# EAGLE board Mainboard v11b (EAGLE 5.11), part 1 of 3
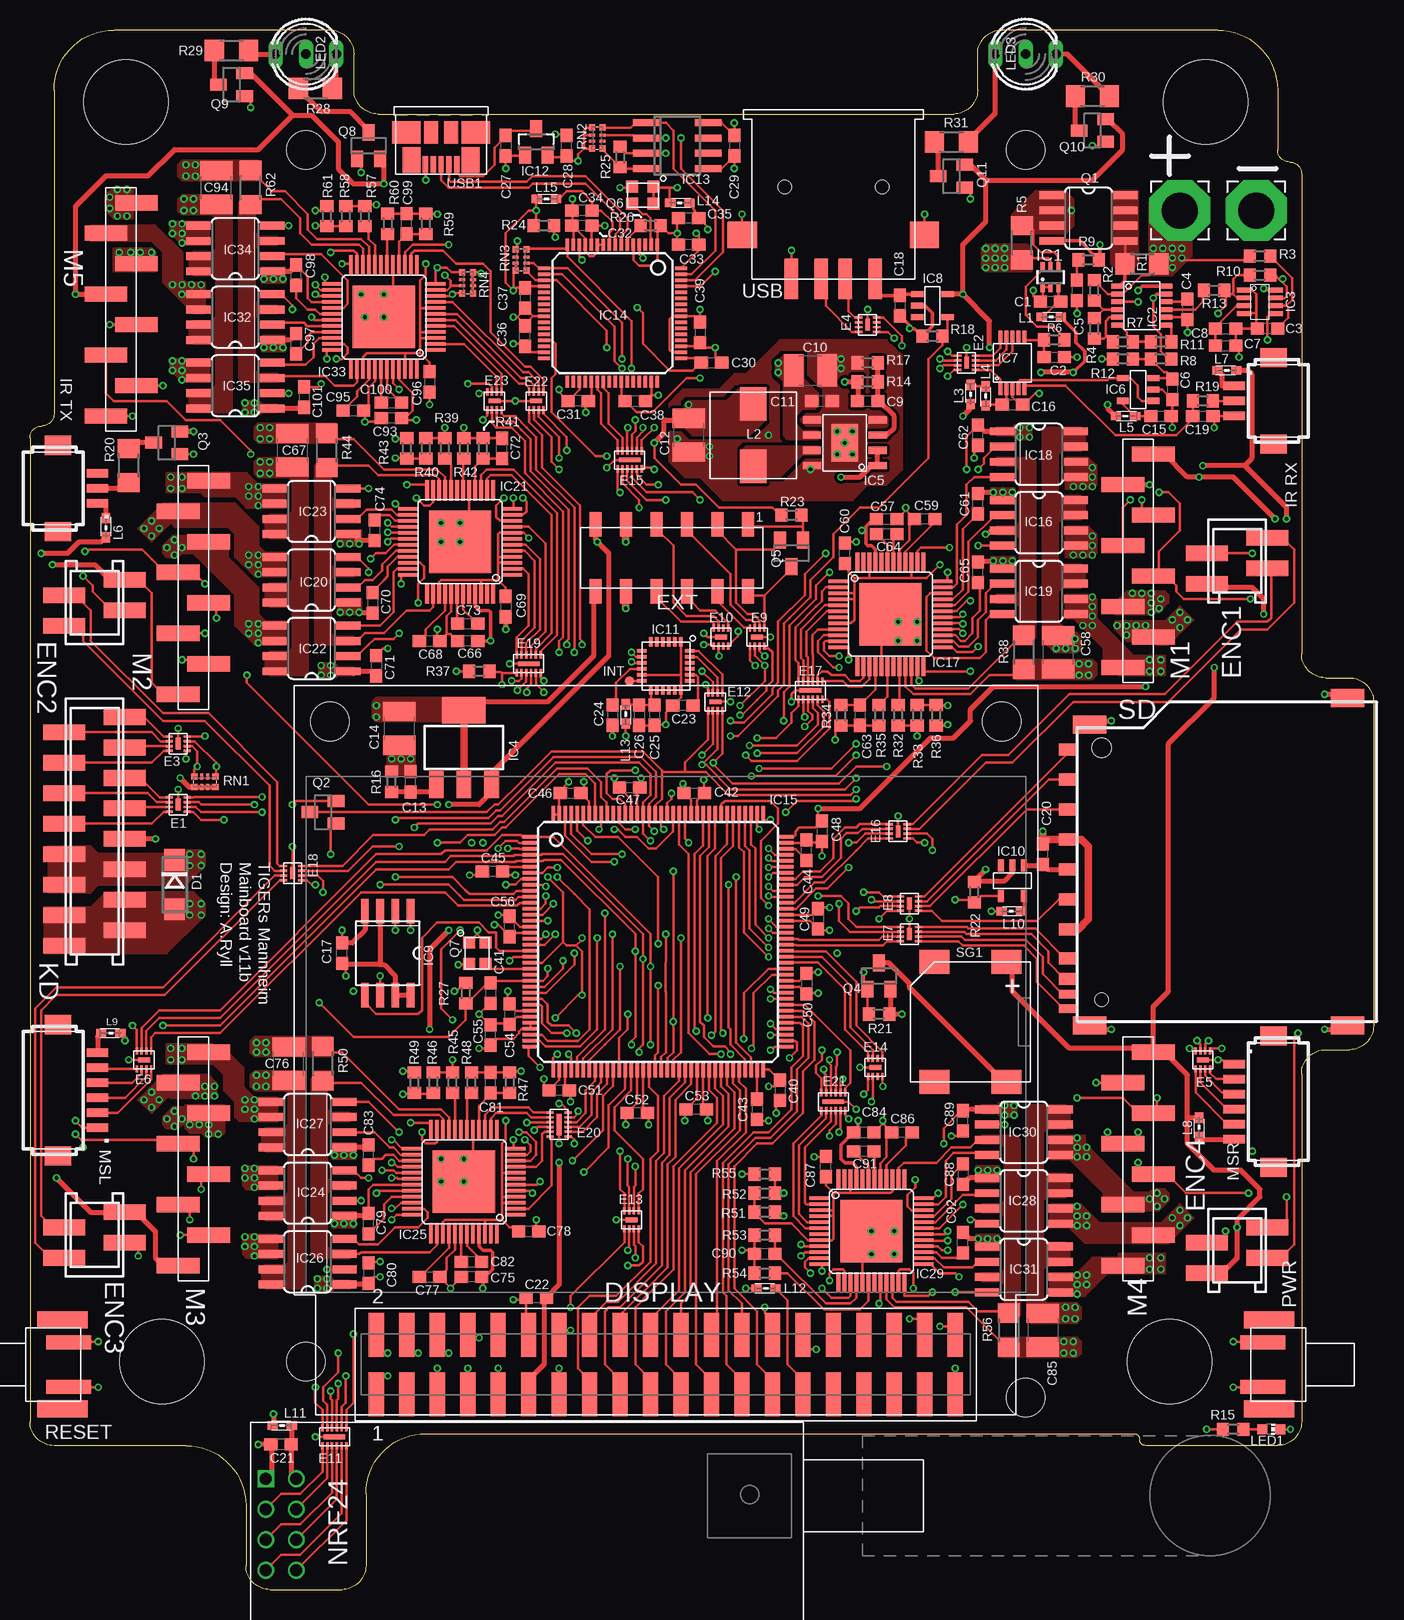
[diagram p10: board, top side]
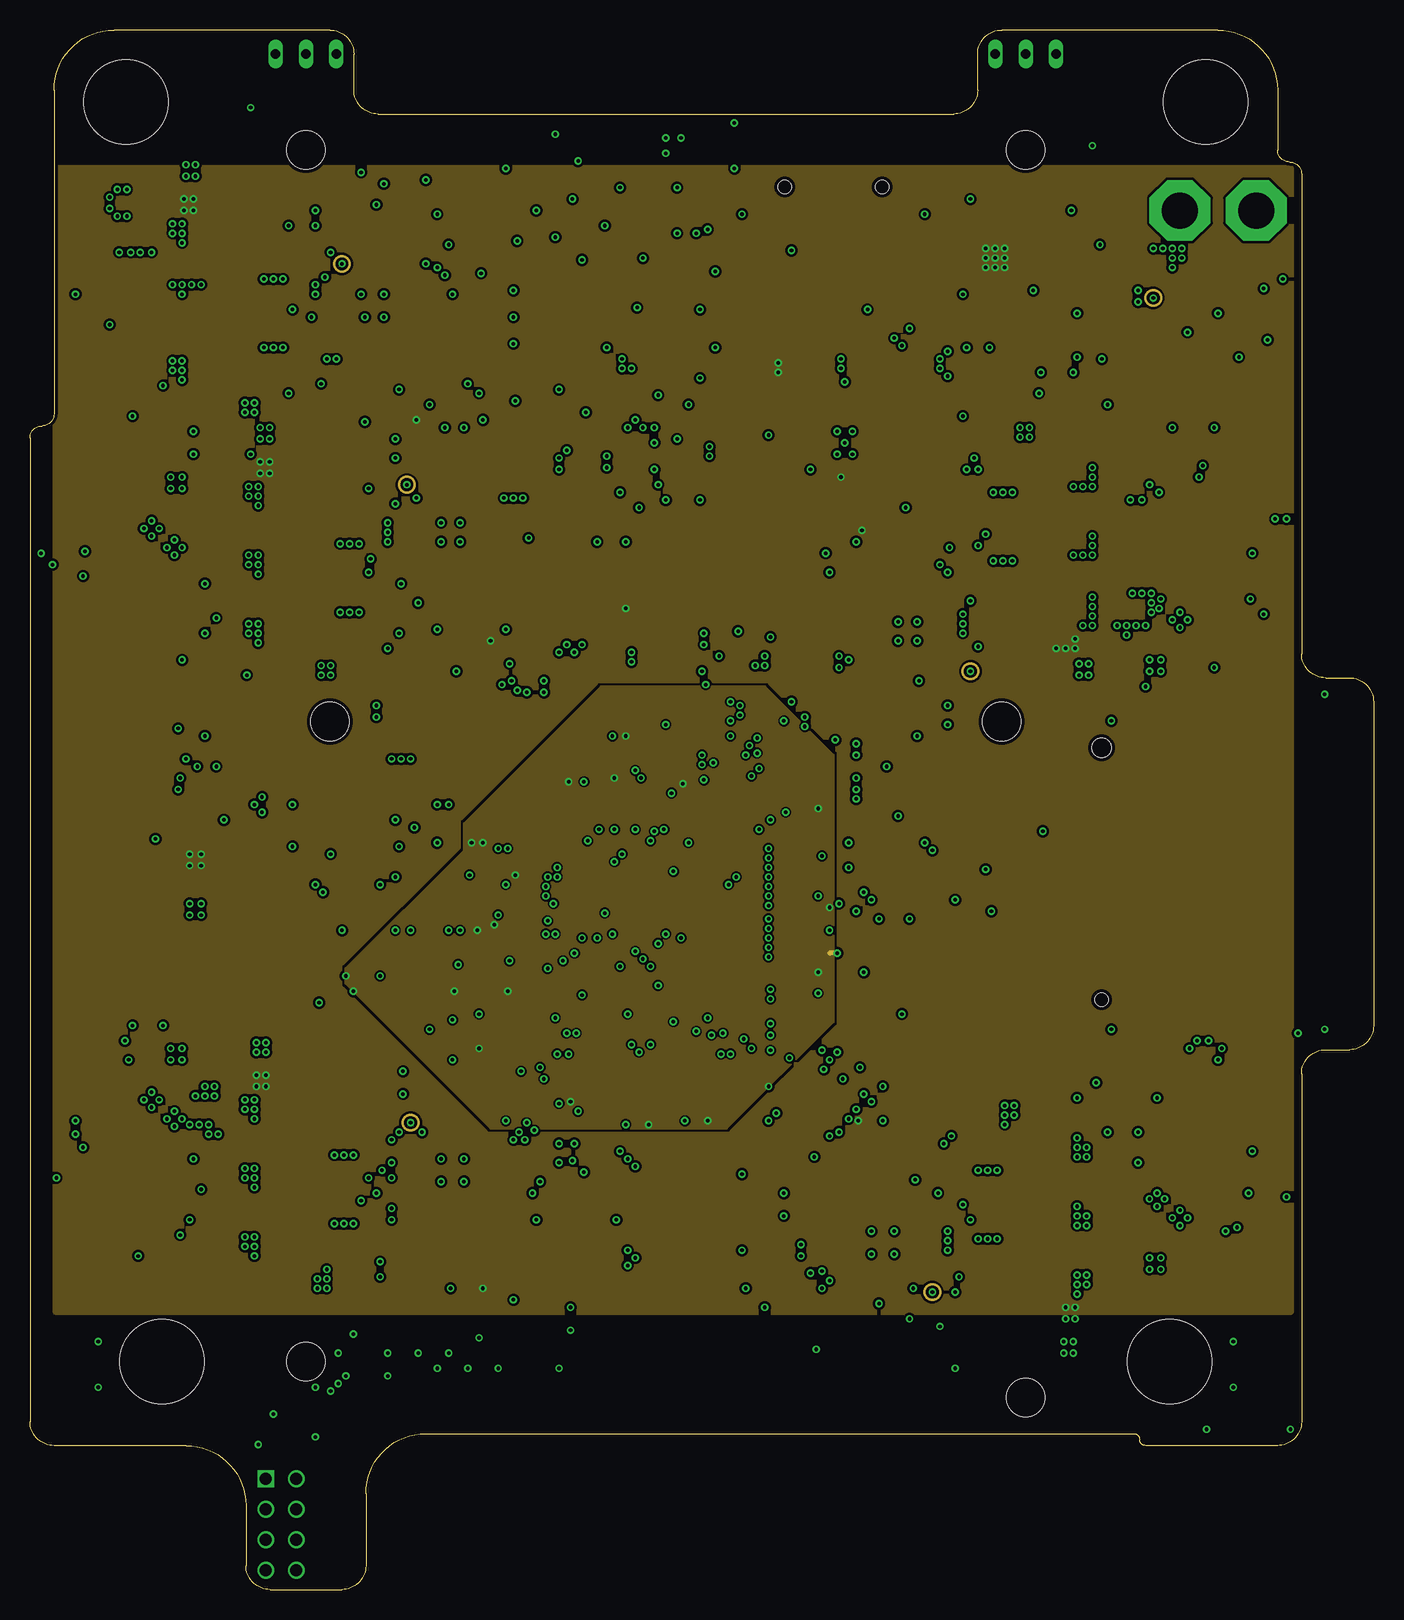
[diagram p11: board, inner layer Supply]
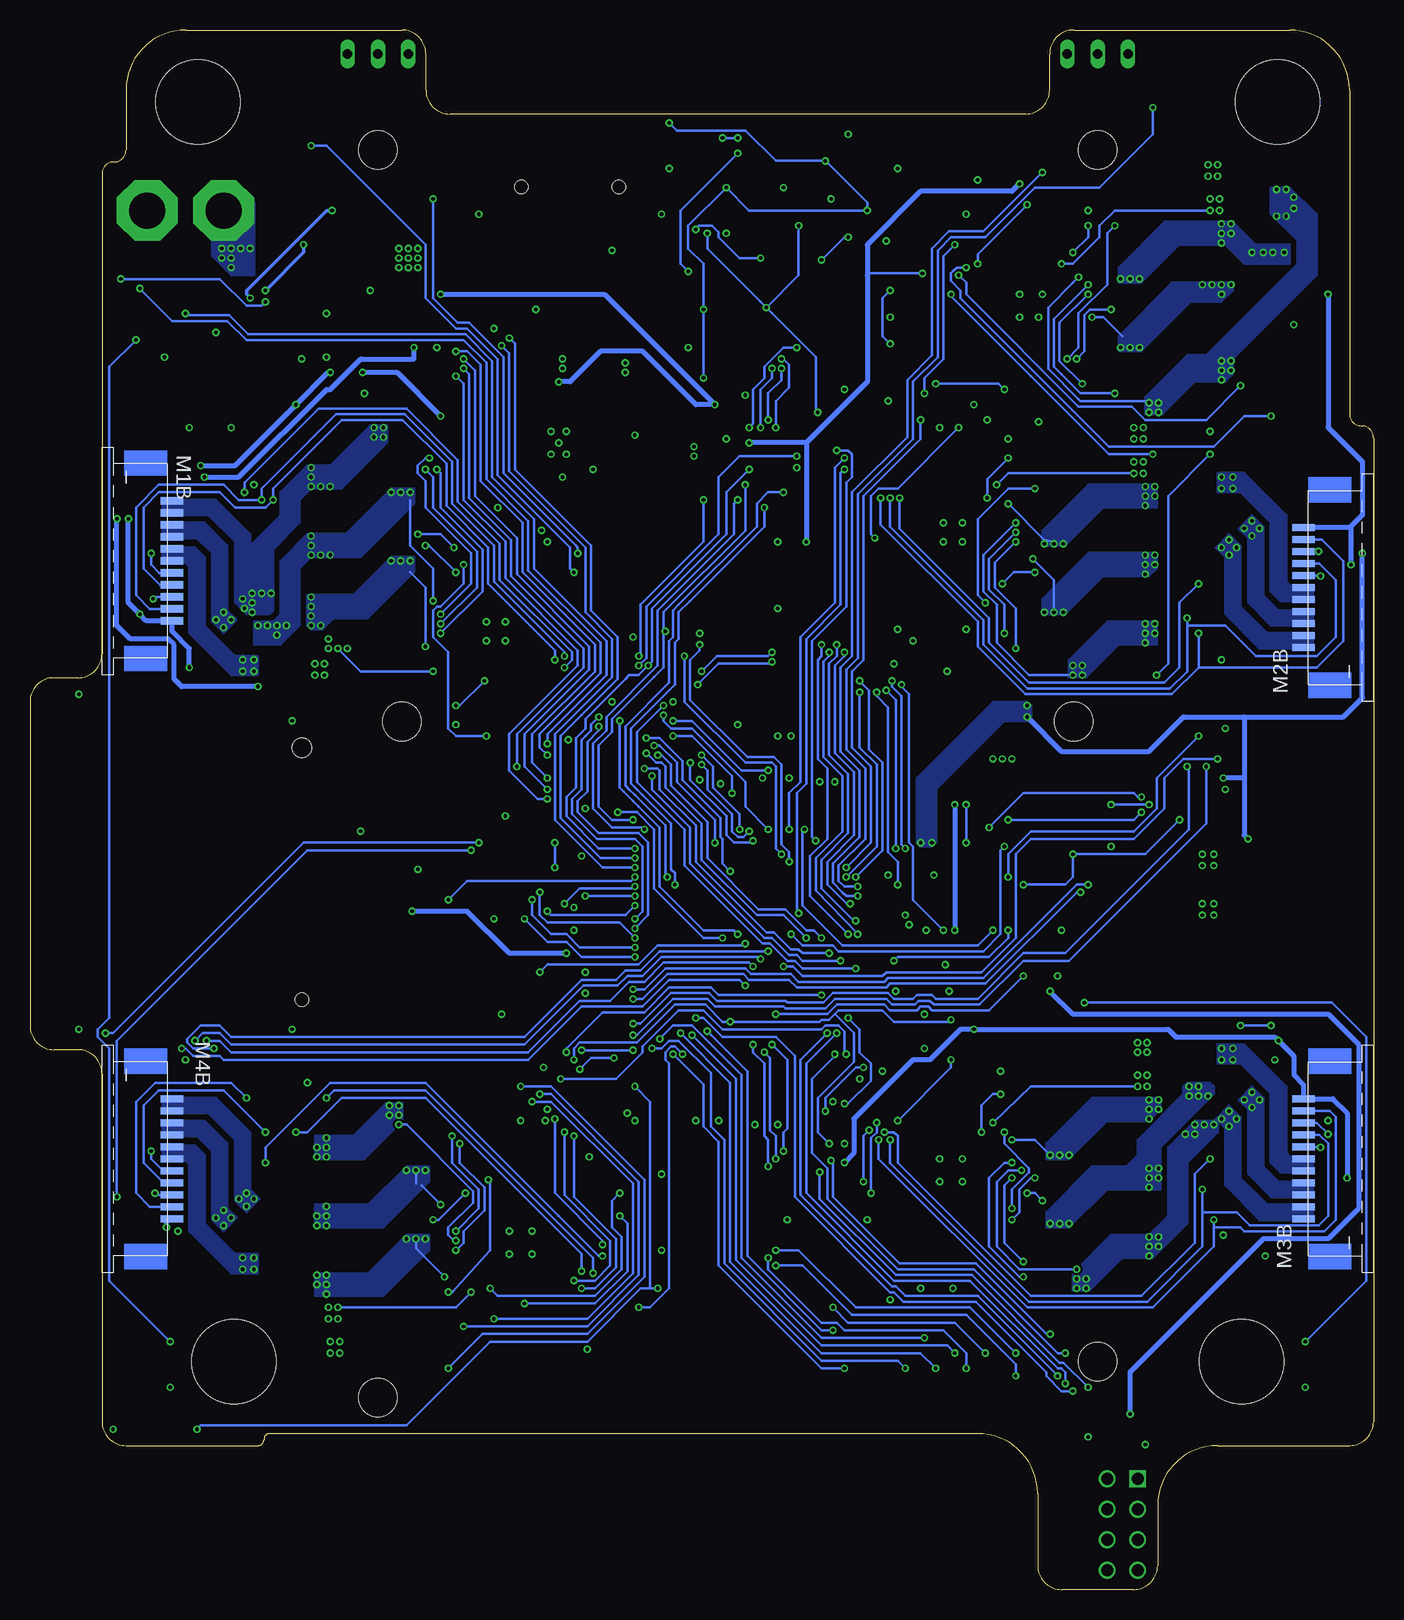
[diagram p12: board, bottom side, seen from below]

Size 112 x 130 mm. Coordinates in mm from the lower left corner, seen from the top.
Outline: 0,96 0,14 arc90 2,12 13,12 arc-90 18,7 18,2 arc90 20,0 26,0 arc90 28,2 28,8 arc-90 33,13 92,13 arc-90 92.5,12.5 arc90 93,12 104,12 arc90 106,14 106,43 arc-90 108,45 110,45 arc90 112,47 112,74 arc90 110,76 108,76 arc-90 106,78 106,118 arc90 105,119 arc-90 104,120 104,125 arc90 99,130 81,130 arc90 79,128 79,125 arc-90 77,123 29,123 arc-90 27,125 27,128 arc90 25,130 7,130 arc90 2,125 2,98 arc-90 1,97 arc90 0,96
Copper layers (1+2*15+16): Top 0.035mm / dielectric 0.38mm / $GND 0.035mm / dielectric 0.71mm / Supply 0.035mm / dielectric 0.38mm / Bottom 0.035mm
Design rules "PCB-POOL Standard_ML4 *": minimum track width 0.15mm, minimum drill 0.3mm, track to track 0.15mm, track to pad 0.15mm, pad to pad 0.15mm, via to via 0.15mm, smd to smd 0.15mm, copper to edge 0.3mm, drill to drill 0.2mm, minimum pad ring 0.2mm, minimum via ring 0.15mm, stop-mask expansion 0.075mm, vias tented up to drill 0mil, thermal gap 0.2mm
Net classes: 0 default: width 0.152 mm, clearance 0.152 mm
Holes 7 mm at 8,124 98,124 95,19 11,19
Holes 3.2 mm at 23,120 83,120 23,19 83,16
tKeepout: area 1.5,117.5 to 14.5,130.5; area 91.5,117.5 to 104.5,130.5; area 4.5,12.5 to 17.5,25.5; area 88.5,12.5 to 101.5,25.5; area 79.6,116.6 to 86.4,123.4; area 19.6,116.6 to 26.4,123.4; area 19.6,15.6 to 26.4,22.4; area 79.6,12.6 to 86.4,19.4

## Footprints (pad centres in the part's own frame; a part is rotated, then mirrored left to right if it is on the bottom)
5,08/3 = drill 3 pad 5.08 octagon: P$1 0,0
C0603 = smd 1.1 x 1: 1 -0.85,0; 2 0.85,0
C1210 = smd 1.6 x 2.7: 1 -1.4,0; 2 1.4,0
DO214AC = smd 1.8 x 1.7: A 2.05,0; C -2.05,0
LT24 = smd 1.27 x 3.683: 1 24.13,2.477; 2 24.13,-2.477; 3 21.59,2.477; 4 21.59,-2.477; 5 19.05,2.477; 6 19.05,-2.477; 7 16.51,2.477; 8 16.51,-2.477; 9 13.97,2.477; 10 13.97,-2.477; 11 11.43,2.477; 12 11.43,-2.477; 13 8.89,2.477; 14 8.89,-2.477; 15 6.35,2.477; 16 6.35,-2.477; 17 3.81,2.477; 18 3.81,-2.477; 19 1.27,2.477; 20 1.27,-2.477; 21 -1.27,2.477; 22 -1.27,-2.477; 23 -3.81,2.477; 24 -3.81,-2.477; 25 -6.35,2.477; 26 -6.35,-2.477; 27 -8.89,2.477; 28 -8.89,-2.477; 29 -11.43,2.477; 30 -11.43,-2.477; 31 -13.97,2.477; 32 -13.97,-2.477; 33 -16.51,2.477; 34 -16.51,-2.477; 35 -19.05,2.477; 36 -19.05,-2.477; 37 -21.59,2.477; 38 -21.59,-2.477; 39 -24.13,2.477; 40 -24.13,-2.477 | hole 3.2: -28,-53.6; 28,-53.6
QFN17X15 = smd 0.2 x 0.6: 1 -0.6,-0.75; 2 -0.6,0.75; 3 -0.2,-0.75; 4 -0.2,0.75; 5 0.2,-0.75; 6 0.2,0.75; 7 0.6,-0.75; 8 0.6,0.75 | smd 1 x 0.4: GND 0,0
QFN25X15 = smd 0.2 x 0.6: 1 -1,-0.75; 2 -1,0.75; 3 -0.6,-0.75; 4 -0.6,0.75; 5 -0.2,-0.75; 6 -0.2,0.75; 7 0.2,-0.75; 8 0.2,0.75; 9 0.6,-0.75; 10 0.6,0.75; 11 1,-0.75; 12 1,0.75 | smd 1.8 x 0.4: GND 0,0
MMT-F-SMD-4 = smd 1.3 x 3.5: 1 1.905,-2.54; 2 0.635,2.54; 3 -0.635,-2.54; 4 -1.905,2.54
XSM-106-DV = smd 1.016 x 2.032: 1 -6.35,-2.794; 2 -6.35,2.794; 3 -3.81,-2.794; 4 -3.81,2.794; 5 -1.27,-2.794; 6 -1.27,2.794; 7 1.27,-2.794; 8 1.27,2.794; 9 3.81,-2.794; 10 3.81,2.794; 11 6.35,-2.794; 12 6.35,2.794
SC70-6L = smd 0.35 x 0.8: 1 -0.65,-0.85; 2 0,-0.85; 3 0.65,-0.85; 4 0.65,0.85; 5 0,0.85; 6 -0.65,0.85
MSOP-12 = smd 0.42 x 0.95: 1 -1.625,-2.075; 2 -0.975,-2.075; 3 -0.325,-2.075; 4 0.325,-2.075; 5 0.975,-2.075; 6 1.625,-2.075; 7 1.625,2.075; 8 0.975,2.075; 9 0.325,2.075; 10 -0.325,2.075; 11 -0.975,2.075; 12 -1.625,2.075
SOT23-8 = smd 1.22 x 0.4: 1 -1.31,0.975; 2 -1.31,0.325; 3 -1.31,-0.325; 4 -1.31,-0.975; 5 1.31,-0.975; 6 1.31,-0.325; 7 1.31,0.325; 8 1.31,0.975
SOT223 = smd 1.219 x 2.235: 1 -2.311,-3.099; 2 0,-3.099; 3 2.311,-3.099 | smd 3.6 x 2.2: 4 0,3.099
HSOP8 = smd 1.524 x 0.61: 1 -2.743,1.905; 2 -2.743,0.635; 3 -2.743,-0.635; 4 -2.743,-1.905; 5 2.743,-1.905; 6 2.743,-0.635; 7 2.743,0.635; 8 2.743,1.905 | smd 2.2 x 3.1: PAD 0,0
SOT23-5 = smd 1.016 x 0.508: 1 -1.27,0.953; 2 -1.27,0; 3 -1.27,-0.953; 4 1.27,-0.953; 5 1.27,0.953
MSOP10-2 = smd 0.3 x 1: 1 -1,-2.2; 2 -0.5,-2.2; 3 0,-2.2; 4 0.5,-2.2; 5 1,-2.2; 6 1,2.2; 7 0.5,2.2; 8 0,2.2; 9 -0.5,2.2; 10 -1,2.2
SO08-208 = smd 0.66 x 2.032: 1 -1.905,-3.498; 2 -0.635,-3.498; 3 0.635,-3.498; 4 1.905,-3.498; 5 1.905,3.498; 6 0.635,3.498; 7 -0.635,3.498; 8 -1.905,3.498
QFN4X4-24 = smd 0.8 x 0.3: 1 -2,1.25; 2 -2,0.75; 3 -2,0.25; 4 -2,-0.25; 5 -2,-0.75; 6 -2,-1.25; 13 2,-1.25; 14 2,-0.75; 15 2,-0.25; 16 2,0.25; 17 2,0.75; 18 2,1.25 | smd 0.3 x 0.8: 7 -1.25,-2; 8 -0.75,-2; 9 -0.25,-2; 10 0.25,-2; 11 0.75,-2; 12 1.25,-2; 19 1.25,2; 20 0.75,2; 21 0.25,2; 22 -0.25,2; 23 -0.75,2; 24 -1.25,2
SOT23 = smd 1 x 1.4: 1 -0.95,-1.1; 2 0.95,-1.1; 3 0,1.1
SO-08 = smd 0.6 x 2.2: 1 -1.905,-2.6; 2 -0.635,-2.6; 3 0.635,-2.6; 4 1.905,-2.6; 5 1.905,2.6; 6 0.635,2.6; 7 -0.635,2.6; 8 -1.905,2.6
LQFP64-ST = smd 1 x 0.3: 1 -5.7,3.75; 2 -5.7,3.25; 3 -5.7,2.75; 4 -5.7,2.25; 5 -5.7,1.75; 6 -5.7,1.25; 7 -5.7,0.75; 8 -5.7,0.25; 9 -5.7,-0.25; 10 -5.7,-0.75; 11 -5.7,-1.25; 12 -5.7,-1.75; 13 -5.7,-2.25; 14 -5.7,-2.75; 15 -5.7,-3.25; 16 -5.7,-3.75; 33 5.7,-3.75; 34 5.7,-3.25; 35 5.7,-2.75; 36 5.7,-2.25; 37 5.7,-1.75; 38 5.7,-1.25; 39 5.7,-0.75; 40 5.7,-0.25; 41 5.7,0.25; 42 5.7,0.75; 43 5.7,1.25; 44 5.7,1.75; 45 5.7,2.25; 46 5.7,2.75; 47 5.7,3.25; 48 5.7,3.75 | smd 0.3 x 1: 17 -3.75,-5.7; 18 -3.25,-5.7; 19 -2.75,-5.7; 20 -2.25,-5.7; 21 -1.75,-5.7; 22 -1.25,-5.7; 23 -0.75,-5.7; 24 -0.25,-5.7; 25 0.25,-5.7; 26 0.75,-5.7; 27 1.25,-5.7; 28 1.75,-5.7; 29 2.25,-5.7; 30 2.75,-5.7; 31 3.25,-5.7; 32 3.75,-5.7; 49 3.75,5.7; 50 3.25,5.7; 51 2.75,5.7; 52 2.25,5.7; 53 1.75,5.7; 54 1.25,5.7; 55 0.75,5.7; 56 0.25,5.7; 57 -0.25,5.7; 58 -0.75,5.7; 59 -1.25,5.7; 60 -1.75,5.7; 61 -2.25,5.7; 62 -2.75,5.7; 63 -3.25,5.7; 64 -3.75,5.7
LQFP144-ST = smd 0.3 x 1.35: 1 -8.75,-10.625; 2 -8.25,-10.625; 3 -7.75,-10.625; 4 -7.25,-10.625; 5 -6.75,-10.625; 6 -6.25,-10.625; 7 -5.75,-10.625; 8 -5.25,-10.625; 9 -4.75,-10.625; 10 -4.25,-10.625; 11 -3.75,-10.625; 12 -3.25,-10.625; 13 -2.75,-10.625; 14 -2.25,-10.625; 15 -1.75,-10.625; 16 -1.25,-10.625; 17 -0.75,-10.625; 18 -0.25,-10.625; 19 0.25,-10.625; 20 0.75,-10.625; 21 1.25,-10.625; 22 1.75,-10.625; 23 2.25,-10.625; 24 2.75,-10.625; 25 3.25,-10.625; 26 3.75,-10.625; 27 4.25,-10.625; 28 4.75,-10.625; 29 5.25,-10.625; 30 5.75,-10.625; 31 6.25,-10.625; 32 6.75,-10.625; 33 7.25,-10.625; 34 7.75,-10.625; 35 8.25,-10.625; 36 8.75,-10.625; 73 8.75,10.625; 74 8.25,10.625; 75 7.75,10.625; 76 7.25,10.625; 77 6.75,10.625; 78 6.25,10.625; 79 5.75,10.625; 80 5.25,10.625; 81 4.75,10.625; 82 4.25,10.625; 83 3.75,10.625; 84 3.25,10.625; 85 2.75,10.625; 86 2.25,10.625; 87 1.75,10.625; 88 1.25,10.625; 89 0.75,10.625; 90 0.25,10.625; 91 -0.25,10.625; 92 -0.75,10.625; 93 -1.25,10.625; 94 -1.75,10.625; 95 -2.25,10.625; 96 -2.75,10.625; 97 -3.25,10.625; 98 -3.75,10.625; 99 -4.25,10.625; 100 -4.75,10.625; 101 -5.25,10.625; 102 -5.75,10.625; 103 -6.25,10.625; 104 -6.75,10.625; 105 -7.25,10.625; 106 -7.75,10.625; 107 -8.25,10.625; 108 -8.75,10.625 | smd 1.35 x 0.3: 37 10.625,-8.75; 38 10.625,-8.25; 39 10.625,-7.75; 40 10.625,-7.25; 41 10.625,-6.75; 42 10.625,-6.25; 43 10.625,-5.75; 44 10.625,-5.25; 45 10.625,-4.75; 46 10.625,-4.25; 47 10.625,-3.75; 48 10.625,-3.25; 49 10.625,-2.75; 50 10.625,-2.25; 51 10.625,-1.75; 52 10.625,-1.25; 53 10.625,-0.75; 54 10.625,-0.25; 55 10.625,0.25; 56 10.625,0.75; 57 10.625,1.25; 58 10.625,1.75; 59 10.625,2.25; 60 10.625,2.75; 61 10.625,3.25; 62 10.625,3.75; 63 10.625,4.25; 64 10.625,4.75; 65 10.625,5.25; 66 10.625,5.75; 67 10.625,6.25; 68 10.625,6.75; 69 10.625,7.25; 70 10.625,7.75; 71 10.625,8.25; 72 10.625,8.75; 109 -10.625,8.75; 110 -10.625,8.25; 111 -10.625,7.75; 112 -10.625,7.25; 113 -10.625,6.75; 114 -10.625,6.25; 115 -10.625,5.75; 116 -10.625,5.25; 117 -10.625,4.75; 118 -10.625,4.25; 119 -10.625,3.75; 120 -10.625,3.25; 121 -10.625,2.75; 122 -10.625,2.25; 123 -10.625,1.75; 124 -10.625,1.25; 125 -10.625,0.75; 126 -10.625,0.25; 127 -10.625,-0.25; 128 -10.625,-0.75; 129 -10.625,-1.25; 130 -10.625,-1.75; 131 -10.625,-2.25; 132 -10.625,-2.75; 133 -10.625,-3.25; 134 -10.625,-3.75; 135 -10.625,-4.25; 136 -10.625,-4.75; 137 -10.625,-5.25; 138 -10.625,-5.75; 139 -10.625,-6.25; 140 -10.625,-6.75; 141 -10.625,-7.25; 142 -10.625,-7.75; 143 -10.625,-8.25; 144 -10.625,-8.75
SOIC8 = smd 0.66 x 2.032: 1 -1.905,-3.073; 2 -0.635,-3.073; 3 0.635,-3.073; 4 1.905,-3.073; 5 1.905,3.073; 6 0.635,3.073; 7 -0.635,3.073; 8 -1.905,3.073
LQFP48-AL = smd 0.3 x 1.7: 1 -2.75,-4.3; 2 -2.25,-4.3; 3 -1.75,-4.3; 4 -1.25,-4.3; 5 -0.75,-4.3; 6 -0.25,-4.3; 7 0.25,-4.3; 8 0.75,-4.3; 9 1.25,-4.3; 10 1.75,-4.3; 11 2.25,-4.3; 12 2.75,-4.3; 25 2.75,4.3; 26 2.25,4.3; 27 1.75,4.3; 28 1.25,4.3; 29 0.75,4.3; 30 0.25,4.3; 31 -0.25,4.3; 32 -0.75,4.3; 33 -1.25,4.3; 34 -1.75,4.3; 35 -2.25,4.3; 36 -2.75,4.3 | smd 1.7 x 0.3: 13 4.3,-2.75; 14 4.3,-2.25; 15 4.3,-1.75; 16 4.3,-1.25; 17 4.3,-0.75; 18 4.3,-0.25; 19 4.3,0.25; 20 4.3,0.75; 21 4.3,1.25; 22 4.3,1.75; 23 4.3,2.25; 24 4.3,2.75; 37 -4.3,2.75; 38 -4.3,2.25; 39 -4.3,1.75; 40 -4.3,1.25; 41 -4.3,0.75; 42 -4.3,0.25; 43 -4.3,-0.25; 44 -4.3,-0.75; 45 -4.3,-1.25; 46 -4.3,-1.75; 47 -4.3,-2.25; 48 -4.3,-2.75 | smd 5.2 x 5.2: TH 0,0
TP08R = smd 0.8 x 0.8: TP 0,0
DF13A-3P-1.25H = smd 1.6 x 2.2: M$0 -3.6,2.4; M$1 3.6,2.4 | smd 0.7 x 1.8: P$1 -1.25,-0.9; P$2 0,-0.9; P$3 1.25,-0.9
MMT-F-SMD-16 = smd 1.3 x 3.5: 1 9.525,-2.54; 2 8.255,2.54; 3 6.985,-2.54; 4 5.715,2.54; 5 4.445,-2.54; 6 3.175,2.54; 7 1.905,-2.54; 8 0.635,2.54; 9 -0.635,-2.54; 10 -1.905,2.54; 11 -3.175,-2.54; 12 -4.445,2.54; 13 -5.715,-2.54; 14 -6.985,2.54; 15 -8.255,-2.54; 16 -9.525,2.54
0603 = smd 0.85 x 0.7: 1 -0.9,0; 2 0.7,0
WE-HCI = smd 2.8 x 2.2: 1 -2.6,0; 2 2.6,0
CHIP-LED0603 = smd 0.8 x 0.8: A 0,-0.75; C 0,0.75
DUOLED5MM = drill 0.813 long: AG -2.54,0; AR 2.54,0; K 0,0
XSM-108-SV = smd 1.27 x 3.556: 1 -8.89,1.27; 2 -6.35,-1.27; 3 -3.81,1.27; 4 -1.27,-1.27; 5 1.27,1.27; 6 3.81,-1.27; 7 6.35,1.27; 8 8.89,-1.27
MOLEX11 = smd 0.6 x 1.9: 1 5,3; 2 4,3; 3 3,3; 4 2,3; 5 1,3; 6 0,3; 7 -1,3; 8 -2,3; 9 -3,3; 10 -4,3; 11 -5,3
DF13A-6P-1.25H = smd 1.6 x 2.2: M$0 -5.475,2.4; M$1 5.475,2.4 | smd 0.7 x 1.8: P$1 -3.125,-0.9; P$2 -1.875,-0.9; P$3 -0.625,-0.9; P$4 0.625,-0.9; P$5 1.875,-0.9; P$6 3.125,-0.9
NRF24L01SLR = drill 1 square: 1 -3.81,1.27 | drill 1 round: 2 -3.81,3.81; 3 -1.27,1.27; 4 -1.27,3.81; 5 1.27,1.27; 6 1.27,3.81; 7 3.81,1.27; 8 3.81,3.81
KT11 = smd 3.759 x 1.168: 1 3.581,1.854; 2 3.581,-1.854 | smd 4.191 x 1.422: MNT1 3.048,3.708; MNT2 3.048,-3.708
CRYSTAL-8W = smd 1 x 1: 1 -0.9,-0.7; 2 0.9,-0.7; 3 0.9,0.7; 4 -0.9,0.7
R1206 = smd 1.6 x 1.803: 1 -1.422,0; 2 1.422,0
R0603 = smd 1 x 1.1: 1 -0.85,0; 2 0.85,0
EXB28V = smd 0.525 x 0.5: 1 -0.875,-0.45; 4 0.875,-0.45; 5 0.875,0.45; 8 -0.875,0.45 | smd 0.25 x 0.5: 2 -0.25,-0.45; 3 0.25,-0.45; 6 0.25,0.45; 7 -0.25,0.45
SDCARD = smd 1 x 1.5: 1 6.875,0.75; 2 4.375,0.75; 3 1.875,0.75; 4 -0.625,0.75; 5 -3.125,0.75; 6 -5.625,0.75; 7 -8.05,0.75; 8 -9.75,0.75; 9 9.375,0.75 | smd 0.7 x 1.5: CD -11.05,0.75; WP -12.25,0.75 | smd 1.5 x 2.8: COM1 -13.65,-1.05; COM2 11.45,-1.05; COM3 -13.65,-22.55; COM4 13.65,-22.55 | hole 1.1: -11.5,-2.05 | hole 1.6: 9.5,-2.05
CSS-95B30 = smd 2.5 x 2: 1 -3,-5; 2 3,-5; 3 3,5; 4 -3,5
USBA-TE = smd 1.12 x 3.39: 1 -3.5,0; 2 -1,0; 3 1,0; 4 3.5,0 | smd 2.44 x 2.22: MNT1 -7.6,-3.68; MNT2 7.6,-3.68 | hole 1.1: -4.06,-7.68; 4.06,-7.68
USB-BMICRO = smd 0.45 x 1.38: 1 1.3,-2.66; 2 0.65,-2.66; 3 0,-2.66; 4 -0.65,-2.66; 5 -1.3,-2.66 | smd 1.175 x 1.9: P$1 0.838,0; P$2 -0.838,0 | smd 2.375 x 1.9: P$3 2.913,0; P$4 -2.913,0 | smd 1.475 x 2.1: P$5 -2.462,-2.3; P$6 2.462,-2.3

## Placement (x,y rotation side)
BAT+  [5,08/3]  95.86,114.96 0 top
BAT-  [5,08/3]  102.21,114.96 0 top
C1  100n  [C0603]  85.07,107.34 180 top
C2  1u  [C0603]  85.38,102.73 0 top
C3  100n  [C0603]  103.16,105.11 180 top
C4  100n  [C0603]  96.5,106.7 270 top
C5  10n  [C0603]  87.29,108.29 270 top
C6  1u  [C0603]  95.23,100.03 270 top
C7  100n  [C0603]  99.67,103.69 0 top
C8  100n  [C0603]  99.67,105.11 0 top
C9  100p  [C0603]  69.83,99.08 0 top
C10  47u  [C1210]  65.06,101.62 0 top
C11  1u  [C0603]  66.02,99.08 0 top
C12  47u  [C1210]  54.91,96.22 270 top
C13  100n  [C0603]  31.73,67.33 90 top
C14  47u  [C1210]  30.77,71.78 270 top
C15  10u  [C0603]  94.28,97.81 0 top
C16  10u  [C0603]  81.89,98.77 0 top
C17  100n  [C0603]  26.01,53.05 90 top
C18  10u  [C0603]  72.53,107.02 270 top
C19  1n  [C0603]  97.77,97.81 0 top
C20  10u  [C0603]  84.43,61.3 90 top
C21  10u  [C0603]  20.93,12.09 180 top
C22  10u  [C0603]  42.2,24.31 180 top
C23  2n2  [C0603]  54.43,73.68 180 top
C24  100n  [C0603]  48.55,72.89 270 top
C25  100n  [C0603]  52.05,72.89 270 top
C26  10u  [C0603]  50.78,72.89 270 top
C27  1u  [C0603]  39.66,120.35 270 top
C28  1u  [C0603]  44.74,120.35 90 top
C29  100n  [C0603]  58.72,120.35 270 top
C30  10u  [C0603]  56.81,102.26 0 top
C31  100n  [C0603]  45.7,99.08 180 top
C32  100n  [C0603]  46.02,113.69 180 top
C33  100n  [C0603]  54.91,112.1 180 top
C34  10u  [C0603]  46.02,114.96 180 top
C35  10u  [C0603]  54.91,114.32 180 top
C36  100n  [C0603]  41.25,104.48 90 top
C37  100n  [C0603]  41.25,107.66 270 top
C38  100n  [C0603]  50.46,99.08 0 top
C39  100n  [C0603]  55.86,104.8 270 top
C40  100n  [C0603]  62.52,41.62 270 top
C41  100n  [C0603]  38.39,49.71 270 top
C42  100n  [C0603]  55.38,66.38 0 top
C43  10u  [C0603]  60.62,40.03 270 top
C44  10u  [C0603]  64.75,61.62 90 top
C45  100n  [C0603]  38.55,59.87 180 top
C46  100n  [C0603]  45.06,66.38 0 top
C47  100n  [C0603]  49.98,66.86 0 top
C48  100n  [C0603]  66.02,63.2 270 top
C49  100n  [C0603]  65.7,55.9 270 top
C50  100n  [C0603]  64.75,50.5 270 top
C51  100n  [C0603]  44.11,41.62 180 top
C52  100n  [C0603]  50.62,39.71 180 top
C53  100n  [C0603]  55.54,40.03 180 top
C54  100n  [C0603]  39.98,47.97 270 top
C55  100n  [C0603]  38.39,46.22 90 top
C56  100n  [C0603]  39.98,55.27 90 top
C57  1u  [C0603]  71.41,89.24 0 top
C58  47u  [C1210]  85.7,78.13 270 top
C59  1u  [C0603]  74.59,89.24 180 top
C60  1u  [C0603]  67.92,86.38 90 top
C61  33n  [C0603]  79.03,90.51 90 top
C62  33n  [C0603]  79.03,96.22 90 top
C63  1n  [C0603]  69.19,72.89 270 top
C64  470n  [C0603]  71.41,87.97 180 top
C65  33n  [C0603]  79.03,84.8 90 top
C66  1u  [C0603]  36.49,79.08 180 top
C67  47u  [C1210]  21.89,94.95 90 top
C68  1u  [C0603]  33.31,79.08 0 top
C69  1u  [C0603]  39.66,81.94 270 top
C70  33n  [C0603]  28.55,82.25 270 top
C71  33n  [C0603]  28.87,77.02 270 top
C72  1n  [C0603]  39.35,95.11 90 top
C73  470n  [C0603]  36.49,80.51 0 top
C74  33n  [C0603]  28.71,88.29 270 top
C75  1u  [C0603]  36.81,26.06 180 top
C76  47u  [C1210]  21.57,43.84 90 top
C77  1u  [C0603]  33.31,26.06 0 top
C78  1u  [C0603]  41.57,29.87 0 top
C79  33n  [C0603]  28.23,30.5 90 top
C80  33n  [C0603]  28.23,26.38 270 top
C81  1n  [C0603]  38.39,42.25 90 top
C82  470n  [C0603]  36.81,27.33 0 top
C83  33n  [C0603]  28.23,36.22 90 top
C84  1u  [C0603]  69.51,38.12 0 top
C85  47u  [C1210]  84.43,21.61 270 top
C86  1u  [C0603]  72.69,38.12 180 top
C87  1u  [C0603]  66.34,35.27 90 top
C88  33n  [C0603]  77.77,34.63 270 top
C89  33n  [C0603]  77.77,39.08 90 top
C90  1n  [C0603]  61.26,27.96 180 top
C91  470n  [C0603]  69.51,36.53 180 top
C92  33n  [C0603]  77.77,28.91 90 top
C93  1u  [C0603]  30.14,97.65 180 top
C94  47u  [C1210]  15.53,116.86 90 top
C95  1u  [C0603]  26.96,98.29 0 top
C96  1u  [C0603]  33.31,100.67 270 top
C97  33n  [C0603]  22.2,103.84 90 top
C98  33n  [C0603]  22.2,109.56 90 top
C99  1n  [C0603]  31.41,113.85 90 top
C100  470n  [C0603]  30.14,98.92 0 top
C101  33n  [C0603]  22.84,99.4 270 top
D1  SMAJ18A  [DO214AC]  12.04,58.76 270 top
DISPLAY  LT24  [LT24]  53,18.76 180 top
E1  EMIF04-1005  [QFN17X15]  12.36,65.43 90 top
E2  EMIF04-1005  [QFN17X15]  78.08,102.26 270 top
E3  EMIF04-1005  [QFN17X15]  12.36,70.51 90 top
E4  EMIF04-1005  [QFN17X15]  69.83,105.43 90 top
E5  EMIF04-1005  [QFN17X15]  97.77,44.16 180 top
E6  EMIF04-1005  [QFN17X15]  9.5,44.16 180 top
E7  EMIF04-1005  [QFN17X15]  73.32,54.63 270 top
E8  EMIF04-1005  [QFN17X15]  73.32,57.17 270 top
E9  EMIF04-1005  [QFN17X15]  60.62,79.4 0 top
E10  EMIF04-1005  [QFN17X15]  57.6,79.4 0 top
E11  EMIF06-1005  [QFN25X15]  25.38,12.72 180 top
E12  EMIF04-1005  [QFN17X15]  57.13,74 0 top
E13  EMIF04-1005  [QFN17X15]  50.14,30.82 0 top
E14  EMIF04-1005  [QFN17X15]  70.46,43.52 0 top
E15  EMIF06-1005  [QFN25X15]  49.98,94.16 180 top
E16  EMIF04-1005  [QFN17X15]  72.37,63.2 270 top
E17  EMIF06-1005  [QFN25X15]  65.06,74.95 0 top
E18  EMIF04-1005  [QFN17X15]  21.89,59.71 90 top
E19  EMIF06-1005  [QFN25X15]  41.57,77.17 0 top
E20  EMIF06-1005  [QFN25X15]  44.11,38.76 90 top
E21  EMIF06-1005  [QFN25X15]  66.97,40.66 180 top
E22  EMIF04-1005  [QFN17X15]  42.2,99.08 0 top
E23  EMIF04-1005  [QFN17X15]  38.71,99.08 0 top
ENC1  [MMT-F-SMD-4]  100.62,85.75 270 top
ENC2  [MMT-F-SMD-4]  5.38,82.25 90 top
ENC3  [MMT-F-SMD-4]  5.38,29.55 90 top
ENC4  [MMT-F-SMD-4]  100.62,28.28 270 top
EXT  SSM-106-L-DV  [XSM-106-DV]  53.5,86 180 top
IC1  INA213BDCK  [SC70-6L]  85.07,109.4 0 top
IC2  LTC4231CMS-2  [MSOP-12]  92.69,107.02 270 top
IC3  LTC2955CTS8-1  [SOT23-8]  102.53,107.34 0 top
IC4  LT3080ST  [SOT223]  36.17,70.19 0 top
IC5  ST1S40IPHR  [HSOP8]  67.92,95.59 180 top
IC6  MCP6001  [SOT23-5]  92.37,100.03 180 top
IC7  ADC124S021  [MSOP10-2]  81.89,102.26 0 top
IC8  STMPS2151STR  [SOT23-5]  75.22,107.02 0 top
IC9  SST25VF016B  [SO08-208]  29.82,53.05 180 top
IC10  STMPS2151STR  [SOT23-5]  81.89,59.08 270 top
IC11  MPU-6000  [QFN4X4-24]  53,77 270 top
IC12  MCP1700T-3302E/TT  [SOT23]  42.2,120.67 0 top
IC13  93LC66B/SN  [SO-08]  53.95,120.35 270 top
IC14  FT2232H  [LQFP64-ST]  48.55,106.38 270 top
IC15  STM32F746ZGT6  [LQFP144-ST]  52.37,54 270 top
IC16  IRF8313  [SOIC8]  84.11,88.92 270 top
IC17  A3930  [LQFP48-AL]  71.73,81.3 270 top
IC18  IRF8313  [SOIC8]  84.11,94.64 270 top
IC19  IRF8313  [SOIC8]  84.11,83.21 270 top
IC20  IRF8313  [SOIC8]  23.47,84.16 90 top
IC21  A3930  [LQFP48-AL]  35.86,87.34 90 top
IC22  IRF8313  [SOIC8]  23.47,78.44 90 top
IC23  IRF8313  [SOIC8]  23.47,89.88 90 top
IC24  IRF8313  [SOIC8]  23.16,33.04 90 top
IC25  A3930  [LQFP48-AL]  36.17,33.99 90 top
IC26  IRF8313  [SOIC8]  23.16,27.33 90 top
IC27  IRF8313  [SOIC8]  23.16,38.76 90 top
IC28  IRF8313  [SOIC8]  82.84,32.41 270 top
IC29  A3930  [LQFP48-AL]  70.14,29.87 270 top
IC30  IRF8313  [SOIC8]  82.84,38.12 270 top
IC31  IRF8313  [SOIC8]  82.84,26.69 270 top
IC32  IRF8313  [SOIC8]  17.12,106.07 90 top
IC33  A3930  [LQFP48-AL]  29.5,106.07 90 top
IC34  IRF8313  [SOIC8]  17.12,111.78 90 top
IC35  IRF8313  [SOIC8]  17.12,100.35 90 top
INT  TPTP08R  [TP08R]  49.98,75.75 0 top
IR1  DF13-3P  [DF13A-3P-1.25H]  4.74,91.78 90 top
IR2  DF13-3P  [DF13A-3P-1.25H]  101.26,99.08 270 top
KD  [MMT-F-SMD-16]  5.38,63.2 270 top
L1  120R  [0603]  85.23,106.07 0 top
L2  10u  [WE-HCI]  60.3,96.22 270 top
L3  27n  [0603]  78.4,99.72 90 top
L4  120R  [0603]  79.67,99.4 270 top
L5  120R  [0603]  91.42,97.81 0 top
L6  120R  [0603]  6.33,88.61 90 top
L7  120R  [0603]  99.67,101.62 180 top
L8  120R  [0603]  97.45,38.44 270 top
L9  120R  [0603]  6.65,46.38 180 top
L10  120R  [0603]  81.89,56.54 0 top
L11  120R  [0603]  20.93,13.67 180 top
L12  120R  [0603]  61.26,25.1 180 top
L13  120R  [0603]  49.67,72.89 270 top
L14  27n  [0603]  54.27,115.59 0 top
L15  27n  [0603]  43.16,115.91 0 top
LED1  gr  [CHIP-LED0603]  103.48,13.36 270 top
LED2  WP59SURKCGKW  [DUOLED5MM]  23,128 0 top
LED3  WP59SURKCGKW  [DUOLED5MM]  83,128 0 top
M1  [XSM-108-SV]  92.37,85.75 90 top
M1B  [MOLEX11]  103.16,85.75 270 bottom
M2  [XSM-108-SV]  13.63,83.53 270 top
M2B  [MOLEX11]  2.84,83.53 90 bottom
M3  [XSM-108-SV]  13.63,35.9 270 top
M3B  [MOLEX11]  2.84,35.9 90 bottom
M4  [XSM-108-SV]  92.37,35.9 90 top
M4B  [MOLEX11]  103.16,35.9 270 bottom
M5  [XSM-108-SV]  7.6,106.7 270 top
MSL  DF13-6P  [DF13A-6P-1.25H]  4.74,41.62 90 top
MSR  DF13-6P  [DF13A-6P-1.25H]  101.26,40.66 270 top
NRF24  NRFL01MOD  [NRF24L01SLR]  18.39,5.42 270 top
PWR  KT11P4SA3M  [KT11]  106.34,18.76 180 top
Q1  IRF8788  [SOIC8]  88.24,114.32 270 top
Q2  BSS84  [SOT23]  24.43,64.79 90 top
Q3  BSS138  [SOT23]  11.41,95.59 90 top
Q4  BSS138  [SOT23]  70.78,51.14 0 top
Q5  BSS138  [SOT23]  63.48,86.38 180 top
Q6  12MHz  [CRYSTAL-8W]  51.09,116.23 180 top
Q7  12MHz  [CRYSTAL-8W]  37.28,53.05 270 top
Q8  BSS84  [SOT23]  28.23,120.35 0 top
Q9  BSS84  [SOT23]  16.8,125.44 90 top
Q10  BSS84  [SOT23]  88.56,121.62 90 top
Q11  BSS84  [SOT23]  76.81,117.81 90 top
R1  0R001  [R1206]  92.69,110.51 180 top
R2  1M  [R0603]  88.72,108.29 270 top
R3  10k  [R0603]  102.53,111.15 180 top
R4  2k2  [R0603]  88.72,105.11 90 top
R5  0R001  [R1206]  82.69,112.26 270 top
R6  1k  [R0603]  85.38,104.16 180 top
R7  47k  [R0603]  91.1,104 180 top
R8  430k  [R0603]  94.28,102.58 0 top
R9  1k  [R0603]  88.24,110.83 0 top
R10  1M  [R0603]  102.53,109.56 0 top
R11  47k  [R0603]  94.28,104 180 top
R12  100k  [R0603]  91.1,102.58 0 top
R13  NA  [R0603]  98.72,108.29 180 top
R14  62k  [R0603]  69.83,100.67 180 top
R15  1k  [R0603]  100.31,13.36 180 top
R16  330k  [R0603]  30.14,67.33 270 top
R17  12k  [R0603]  69.83,102.26 0 top
R18  10k  [R0603]  75.22,104.48 0 top
R19  1k  [R0603]  97.77,99.08 180 top
R20  47  [R1206]  8.23,93.69 270 top
R21  10k  [R0603]  70.78,47.97 180 top
R22  10k  [R0603]  78.72,58.12 90 top
R23  10k  [R0603]  63.48,89.56 180 top
R24  10k  [R0603]  42.84,113.69 180 top
R25  2k2  [R0603]  49.19,119.4 90 top
R26  12k  [R0603]  51.73,113.69 180 top
R27  10k  [R0603]  36.33,49.71 90 top
R28  120  [R1206]  23.79,125.12 180 top
R29  120  [R1206]  16.8,128.29 180 top
R30  120  [R1206]  88.56,124.48 180 top
R31  120  [R1206]  76.81,120.67 180 top
R32  100k  [R0603]  72.37,72.89 270 top
R33  150k  [R0603]  73.95,72.89 270 top
R34  47k  [R0603]  67.61,72.89 90 top
R35  10k  [R0603]  70.78,72.89 90 top
R36  10k  [R0603]  75.54,72.89 90 top
R37  10k  [R0603]  37.44,76.54 0 top
R38  0R02  [R1206]  82.84,78.13 90 top
R39  100k  [R0603]  34.59,95.11 90 top
R40  150k  [R0603]  33,95.11 90 top
R41  47k  [R0603]  37.76,95.11 270 top
R42  10k  [R0603]  36.17,95.11 270 top
R43  10k  [R0603]  31.41,95.11 270 top
R44  0R02  [R1206]  24.74,94.95 270 top
R45  100k  [R0603]  35.22,42.25 90 top
R46  150k  [R0603]  33.63,42.25 90 top
R47  47k  [R0603]  39.98,42.25 270 top
R48  10k  [R0603]  36.81,42.25 270 top
R49  10k  [R0603]  32.05,42.25 270 top
R50  0R02  [R1206]  24.43,43.84 270 top
R51  100k  [R0603]  61.26,31.45 180 top
R52  150k  [R0603]  61.26,33.04 180 top
R53  47k  [R0603]  61.26,29.55 0 top
R54  10k  [R0603]  61.26,26.38 0 top
R55  10k  [R0603]  61.26,34.63 0 top
R56  0R02  [R1206]  81.58,21.61 90 top
R57  100k  [R0603]  27.92,114.48 90 top
R58  150k  [R0603]  26.33,114.48 90 top
R59  47k  [R0603]  33,113.85 270 top
R60  10k  [R0603]  29.82,113.85 270 top
R61  10k  [R0603]  24.74,114.48 270 top
R62  0R02  [R1206]  18.39,116.86 270 top
RESET  KT11P4SA3M  [KT11]  -0.34,18.76 0 top
RN1  10k  [EXB28V]  14.58,67.33 180 top
RN2  10k  [EXB28V]  47.28,120.99 90 top
RN3  10k  [EXB28V]  40.94,110.83 90 top
RN4  10k  [EXB28V]  36.49,108.92 270 top
SD  SDCARD  [SDCARD]  87.29,60.66 90 top
SG1  CSS-95B30  [CSS-95B30]  78.4,47.33 180 top
USB  [USBA-TE]  66.97,109.24 180 top
USB1  USB-BU  [USB-BMICRO]  34.27,121.47 0 top

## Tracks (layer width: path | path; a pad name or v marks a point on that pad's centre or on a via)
12MHZ
  Top 0.203: 37.98,52.03 Q7.3 38.38,51.75 IC15.23
+3V3  (via drill 0.3)
  Top 0.203: IC15.108 63.66,62.75 63.8,62.89 63.8,63.2 64.11,63.52 65.48,63.52 C48.1 65.7,64.37 v65.7,65.11 | IC15.95 65.19,56.25 C49.1 65.8,56.86 v66.65,56.86 | IC15.84 64.14,50.75 C50.1 64.85,51.46 v65.7,51.46 | C40.1 62.84,42.62 | IC15.62 56.12,40.3 C53.1 56.49,39.92 v56.49,39.08 | IC15.52 51.12,40.06 C52.1 51.57,39.61 v51.57,38.76 | IC15.39 44.62,41.96 C51.1 45.06,41.51 v45.06,40.66 | IC15.32 IC15.33 40.99,46.75 40.78,46.54 40.78,46.38 40.3,45.9 38.93,45.9 C55.1 38.13,45.11 v37.44,45.11 | IC15.30 40.55,48.25 C54.1 39.82,48.97 v39.82,49.87 | IC15.144 IC15.143 44.12,66.28 C46.1 44.11,66.48 v44.9,67.33 | IC15.131 50.12,65.88 C47.1 48.71,66.96 v48.71,67.65 | IC15.121 55.12,65.8 C42.1 54.43,66.48 v54.43,67.17 | 37.28,54.64 Q7.1 | Q7.4 37.28,54.64 | 37.28,54.64 v37.28,54.95 | IC15.17 40.1,54.75 39.66,54.31 39.88,54.31 C56.1 39.98,54.47 39.03,55.43 v38.71,55.43 | IC15.6 39.66,60.25 | 39.66,60.25 C45.1 39.72,59.55 v40.46,59.55 | v80.15,56.54 L10.1 | 26.11,52.09 26.33,51.83 v26.33,51.14 | 39.66,60.25 39.35,59.93 | L13.2 v49.67,71.14 | R27.2 36.23,50.56 35.54,49.87 v35.38,49.87 | v61.57,41.93 61.99,41.93 C40.1 | IC15.72 61.62,43.37 C40.1 | R15.2 v98.09,13.36 | v59.67,25.1 L12.2
  Top 0.305: v86.97,101.46 87.92,102.42 87.92,103.21 87.2,103.94 87.2,104.8 L1.2
  Top 0.406: IC9.8 IC9.7 30.46,51.14 29.5,52.09 29.19,52.09 | 29.19,52.09 26.11,52.09 C17.1 | IC9.3 29.19,52.09 | RN1.8 RN1.7 RN1.6 RN1.5 13.29,66.88 v12.52,67.65 | v10.45,62.57 KD.8 | v65.7,65.11 69.19,65.11 75.07,70.98 76.97,70.98 78.4,72.41 78.4,73.36 80.31,75.27 v93,75.27 | L3.1 78.4,98.45 v77.77,97.81 | v86.97,101.46 v84.27,101.46 | L11.2 20.3,13.74 v20.3,14.63 | v0.93,86.38 3.15,86.38 4.1,87.34 5.96,87.34 L6.1 | v104.75,89.24 104.75,90.19 101.26,93.69 | L7.1 101.58,101.62 101.9,101.31 101.9,94.32 101.26,93.69 | 101.26,93.69 v97.77,93.69 | L5.1 89.83,98.5 v89.83,98.77 | EXT.12 47.15,82.75 46.97,82.57 46.97,77.81 43.16,74 36.88,74 IC4.4
  Top 0.61: IC4.4 IC4.2
  Supply 0.406: v67.29,53.05 66.65,53.05
  Bottom 0.203: v98.09,13.36 97.77,13.67 80.62,13.67 73.64,20.66 65.54,20.66 61.1,25.1 L12.2 | v61.57,41.93 60.3,40.66 60.3,25.1 L12.2 | L12.2 v59.67,25.1
  Bottom 0.406: v10.45,62.57 10.77,62.89 10.77,67.65 | v80.15,56.54 75.54,56.54 72.05,53.05 v67.29,53.05 | v77.77,97.81 81.42,101.46 83.64,101.46 | 83.64,101.46 | v84.27,101.46 83.64,101.46 | v28.87,72.73 26.01,69.87 18.71,69.87 15.85,72.73 10.77,72.73 | 10.77,67.65 v12.52,67.65 | v20.3,14.63 20.3,18.12 9.19,29.23 3.79,29.23 1.25,31.77 1.25,45.42 3.79,47.97 25.06,47.97 v26.96,49.87 | v104.75,89.24 104.75,80.35 103.64,79.24 100.47,79.24 99.99,78.76 99.99,75.91 99.35,75.27 v93,75.27 | 10.77,72.73 2.52,72.73 0.93,74.32 v0.93,86.38 | 10.77,72.73 10.77,67.65 | v97.77,93.69 94.91,93.69 v89.83,98.77 87.13,101.46 v86.97,101.46
  other vias: 28.87,73.68 36.81,62.25 37.76,62.25
  pour Supply (rank 2): 47.6,75.27 61.26,75.27 66.97,69.56 66.97,47.33 58.08,38.44 38.39,38.44 26.33,50.5 26.33,51.77 36.17,61.62 36.17,63.84
  pour Top (no thermals): 28.55,74 28.87,74.32 37.44,74.32 37.44,72.41 28.87,72.41 28.55,72.73
  pour Bottom (no thermals): 28.87,74 31.73,74 38.08,67.65 38.08,62.25 37.76,61.94 36.81,61.94 36.49,62.25 36.49,66.7 30.77,72.41 28.87,72.41 28.55,72.73 28.55,73.68
+5V  (via drill 0.3)
  Top 0.203: 41.57,17.48 DISPLAY.11 | C22.1 42.84,24.1 | RN4.5 RN4.6 RN4.7 RN4.8 37.52,109.8 v37.6,109.72 | R23.2 62.52,89.56 61.89,90.19 57.45,90.19 55.54,92.1 54.27,92.1 52.05,94.32 v52.05,95.59 | ENC2.1 9.03,84.16 10.14,83.05 10.14,75.59 10.77,74.95 12.04,74.95 M2.8
  Top 0.406: 41.57,17.48 42.84,18.76 42.84,24.1 | C22.1 43.05,24.37 44.11,25.42 v44.11,35.58 | v33.31,46.7 33.31,53.36 v34.9,54.95 | IC4.3 38.39,67.18 | v52.05,95.59 52.84,96.38 52.84,97.34 53,97.5 54.77,97.5 C12.1 | v79.99,103.53 79.99,105.75 v77.77,107.97 | v34.9,65.43 37.44,65.43 38.39,66.38 38.39,67 IC4.3 | v103.8,89.24 100.31,92.73 v97.45,92.73 96.5,92.73 94.59,94.64 M1.8 | v98.72,76.86 98.72,74.32 94.91,70.51 94.91,49.87 93.64,48.6 M4.8 | v67.92,100.67 R14.2 69.03,100.61 69.03,99.14 C9.1 | L9.1 7.91,46.01 v7.91,45.74 | v77.77,107.97 IC8.5 | Q8.2 29.18,118.77 29.5,118.77 v29.5,117.18 26.96,117.18 25.7,118.45 25.7,120.67 23.47,122.9 21.89,122.9 | Q9.2 18.4,126.38 21.89,122.9 | Q10.2 89.83,122.58 91.1,121.31 91.1,120.04 88.56,117.5 79.67,117.5 | 79.67,117.5 79.67,114 77.77,112.1 v77.77,107.97 | Q11.2 78.4,118.77 79.67,117.5 | SG1.1 81.89,51.84 81.89,49.87 86.66,45.11 93.32,45.11 M4.8 | IC4.3 38.48,68.06 48.24,77.81 48.24,86.38 v47.28,87.34 47.15,87.47 EXT.11 | M5.4 v3.79,107.97 3.79,115.28 6.33,117.81 9.82,117.81 12.04,120.04 19.03,120.04 21.89,122.9 | v1.88,85.43 5.38,85.43 6.65,84.16 ENC2.1 | ENC1.1 99.35,83.84 99.67,83.53 101.9,83.53 102.85,82.57 v102.85,81.3 | ENC4.1 99.35,26.38 100.62,27.65 v100.62,30.19 100.62,30.82 102.53,32.73 102.53,33.36 100.94,34.95 98.72,34.95 96.5,37.17 96.5,39.39 | 96.5,39.39 96.5,42.89 94.59,44.79 M4.8 | L8.1 96.55,39.34 96.5,39.39 | v2.2,34.31 5.06,31.45 ENC3.1 8.87,31.45 10.45,29.87 10.45,27.65 11.09,27.01 M3.8
  Bottom 0.203: v37.6,109.72 42.05,109.72 42.2,109.56
  Bottom 0.406: v44.11,35.58 43.32,36.38 43.32,39.23 38.39,44.16 36.97,44.16 34.43,46.7 v33.31,46.7 17.12,46.7 16.49,46.06 8.23,46.06 v7.91,45.74 6.65,44.47 6.65,42.89 5.84,42.08 M3B.1 3.39,40.9 2.2,39.71 v2.2,34.31 | v34.9,65.43 v34.9,54.95 | 55.54,99.4 64.11,107.97 v77.77,107.97 | v79.99,103.53 79.99,102.58 84.43,102.58 86.97,100.03 87.29,100.03 94.59,92.73 v97.45,92.73 | v98.72,76.86 98.72,78.44 100.16,79.89 M1B.1 102.29,80.75 v102.85,81.3 103.8,82.25 v103.8,89.24 | 55.54,99.4 | 55.54,99.4 v54.91,98.77 56.49,98.77 60.94,103.21 64.43,103.21 66.97,100.67 v67.92,100.67 | 47.28,95.59 42.2,100.67 42.2,109.56 42.2,112.1 37.76,116.55 30.14,116.55 v29.5,117.18 | 47.28,95.59 v47.28,87.34 | 47.28,95.59 v52.05,95.59 | v3.79,107.97 3.79,96.86 0.93,94 0.93,89.56 1.88,88.61 | 1.88,88.61 v1.88,85.43 | M2B.1 1.96,88.53 1.88,88.61 | M4B.1 100.62,30.9 v100.62,30.19
  pour Top (no thermals): 61.26,100.03 59.03,100.03 58.08,99.08 54.91,99.08 54.59,98.77 54.59,96.86 55.22,96.22 59.98,96.22 61.26,97.5
AUX_CS  (via drill 0.3)
  Top 0.203: E2.7 77.01,101.66 v76.5,101.15 | IC15.57 53.62,44.14 54.27,44.79 v54.27,54.31 | v63,64.79 63.95,65.75 68.72,65.75 v68.88,65.9
  Bottom 0.203: v63,64.79 61.41,64.79 59.98,63.36 59.98,58.44 55.86,54.31 v54.27,54.31 | v68.88,65.9 69.67,65.9 72.05,68.28 72.05,71.3 66.34,77.02 66.34,78.29 72.37,84.32 72.37,87.34 75.86,90.83 75.86,100.51 v76.5,101.15
BAT+  (via drill 0.3)
  Top 0.203: R1.1 94.11,110.35 | R2.1 89.86,108 IC2.2 91.12,108 92.69,109.56 93.32,109.56 | R3.2 101.36,110.83 96.18,110.83 v96.02,110.99 | 95.86,113.27 BAT+.P$1
  other vias: 95.23,110.19 95.23,110.99 95.23,111.78 96.02,111.78 94.43,111.78 93.64,111.78
  pour Top (no thermals): 93.32,115.59 93.32,109.56 95.23,109.56 96.81,111.15 96.81,115.59
  pour Bottom (no thermals): 93.32,109.56 95.23,109.56 96.81,111.15 96.81,115.59 93.32,115.59
BAT_ADC
  Top 0.203: IC6.3 95.12,100.99 C6.1 95.23,100.99 94.75,101.46 94.54,101.46 R8.1 R12.2
DRIB_MODE  (via drill 0.3)
  Top 0.203: IC15.7 42.72,59.75 43.16,60.19 v43.95,60.19 | v37.76,97.5 38.11,97.85 E23.1
  Bottom 0.203: v43.95,60.19 41.89,62.25 41.89,68.6 43.48,70.19 43.48,76.54 42.52,77.49 42.52,91.14 37.76,95.91 v37.76,97.5
DRIB_RESET  (via drill 0.3)
  Top 0.203: 40.94,96.7 40.3,97.34 39.19,97.34 38.91,97.61 E23.5 | 40.94,96.7 | 40.94,96.7 41.73,95.91 41.73,93.21 44.9,90.03 44.9,79.24 44.74,79.08 v44.74,78.76 | IC15.15 43,55.75 v43.16,55.74
  Bottom 0.203: v43.16,55.74 43.32,55.74 46.02,58.44 46.02,60.82 43.79,63.05 43.79,67.97 45.38,69.56 45.38,77.17 44.74,77.81 v44.74,78.76
DRIVE_MODE  (via drill 0.3)
  Top 0.203: E19.11 42.57,76.02 v42.84,75.75 | IC15.22 42.68,52.25 44.43,54 | 44.43,54 44.43,58.12 v43.16,59.39 | E20.11 44.86,39.91 44.27,40.5 v44.11,40.5 | 45.54,53.68 46.02,53.2 v46.02,49.55 45.7,49.55 v43.79,47.65 | 45.54,53.68 44.74,53.68 44.43,54 | E17.11 66.45,74.2 66.65,74 66.65,71.78 66.18,71.3 | 66.18,71.3 | v46.02,54.31 46.02,54.16 45.54,53.68 | v59.67,69.56 60.14,69.08 63.95,69.08 66.18,71.3 | E21.5 67.17,43.56 67.29,43.68 v67.29,44.79
  Bottom 0.203: v43.16,59.39 40.94,61.62 40.94,68.92 42.05,70.03 42.05,74.95 v42.84,75.75 | v46.02,49.55 48.87,49.55 | 48.87,49.55 | 48.87,49.55 54.59,49.55 55.22,50.19 58.72,50.19 60.78,48.12 64.27,48.12 67.29,45.11 v67.29,44.79 | v46.02,54.31 46.65,54.95 47.28,54.95 49.03,56.7 51.25,56.7 55.54,60.98 55.54,64 58.56,67.02 58.56,68.76 59.35,69.56 v59.67,69.56 | v43.79,47.65 42.84,46.7 42.84,44.79 41.89,43.84 41.89,42.41 43.79,40.5 v44.11,40.5
DRIVE_RESET  (via drill 0.3)
  Top 0.203: IC15.56 53.16,43.42 53.16,44.31 53.63,44.79 v53.63,47.33 v53.63,59.87 | R37.2 38.29,76.48 39.24,76.48 39.35,76.38 | v39.35,75.43 39.35,76.38 | v35.86,54.95 34.27,53.36 34.27,48.44 v35.22,47.49 | E19.1 40.57,76.38 39.35,76.38 | E20.1 45.11,37.76 45.38,37.49 v45.38,37.17 | v60.62,70.98 62.21,70.98 63.48,72.25 63.48,73.05 64.06,73.64 E17.1 | v66.65,44.16 66.65,43.84 66.77,43.72 E21.7
  Bottom 0.203: v39.35,75.43 39.35,75.27 38.71,74.64 38.71,62.25 38.39,61.94 38.39,57.49 v35.86,54.95 | v53.63,59.87 54.27,60.51 54.27,62.57 54.43,62.73 54.43,64.32 57.6,67.49 57.6,69.08 59.51,70.98 v60.62,70.98 | v45.38,37.17 46.33,38.12 46.33,40.98 43.32,44 43.32,46.38 44.9,47.97 | 44.9,47.97 45.38,47.49 46.02,47.49 46.17,47.33 v53.63,47.33 54.27,47.33 55.7,48.76 58.24,48.76 61.41,45.58 66.18,45.58 66.65,45.11 v66.65,44.16 | 44.9,47.97 44.59,48.28 40.94,48.28 39.98,47.33 35.38,47.33 v35.22,47.49
EXT_DETECT
  Top 0.203: 64.43,87.33 Q5.1 64.43,88.61 | R23.1 64.43,89.46 64.43,88.61 | EXT.1 59.85,88.61 64.43,88.61
FB2
  Top 0.406: R17.2 R14.1 C9.2 70.78,99.08 72.05,97.81 72.05,96.86 71.41,96.22 IC5.3
FMC_A7
  Top 0.203: DISPLAY.15 46.65,17.48 45.7,18.44 45.7,23.52 46.65,24.47 48.87,24.47 51.73,27.33 51.73,35.9 52.37,36.53 52.37,41.14 51.62,41.89 IC15.53
FMC_D0  (via drill 0.3)
  Top 0.203: IC15.85 61.84,51.25 60.3,49.71 60.3,45.27 v60.14,45.11 | v39.03,18.44 DISPLAY.9
  Bottom 0.203: v39.03,18.44 39.66,19.07 46.02,19.07 54.11,27.17 54.11,37.49 55.22,38.6 55.22,43.04 57.92,45.74 58.72,45.74 59.35,45.11 v60.14,45.11
FMC_D1  (via drill 0.3)
  Top 0.203: IC15.86 61.55,51.75 59.51,49.71 v59.51,45.9 | DISPLAY.8 36.55,21.23 36.81,20.98 v37.44,20.98
  Bottom 0.203: v59.51,45.9 58.4,47.01 56.81,47.01 52.68,42.89 52.68,27.65 46.02,20.98 v37.44,20.98
FMC_D2  (via drill 0.3)
  Top 0.203: IC15.114 58.62,61.99 57.6,60.98 57.6,46.54 v57.76,46.38 | v36.49,18.44 DISPLAY.7
  Bottom 0.203: v36.49,18.44 37.76,19.71 46.02,19.71 53.63,27.33 53.63,42.25 v57.76,46.38
FMC_D3  (via drill 0.3)
  Top 0.203: IC15.115 58.12,62.13 57.13,61.14 57.13,46.54 v56.81,46.22 | DISPLAY.6 33.95,20.02 34.27,19.71 v34.9,19.71
  Bottom 0.203: v34.9,19.71 35.54,20.34 46.02,20.34 53.16,27.49 53.16,42.57 v56.81,46.22
FMC_D4
  Top 0.203: IC15.58 54.12,42.41 52.84,41.14 52.84,36.38 52.21,35.74 52.21,27.17 49.03,23.99 48.08,23.99 46.65,22.56 DISPLAY.16
FMC_D5
  Top 0.203: DISPLAY.17 49.19,17.48 47.92,18.76 47.92,23.2 48.24,23.52 49.19,23.52 52.68,27.01 52.68,35.58 53.32,36.22 53.32,40.98 54.62,42.28 IC15.59
FMC_D6
  Top 0.203: IC15.60 55.12,42.14 53.79,40.82 53.79,36.06 53.16,35.42 53.16,26.85 51.25,24.95 50.94,24.63 49.19,22.88 DISPLAY.18
FMC_D7
  Top 0.203: DISPLAY.19 51.73,17.48 50.46,18.76 50.46,23.52 51.09,24.15 51.41,24.47 53.63,26.69 53.63,35.27 57.29,38.92 57.29,40.98 56.62,41.65 56.62,42.29 IC15.63
FMC_D8
  Top 0.203: IC15.64 57.12,41.79 57.76,41.14 57.76,38.76 54.11,35.11 54.11,31.14 54.11,30.82 54.11,24.95 51.73,22.56 DISPLAY.20
FMC_D9
  Top 0.203: DISPLAY.21 54.27,17.48 53,18.76 53,23.2 54.59,24.79 54.59,34.95 58.24,38.6 58.24,41.3 57.62,41.92 IC15.65
FMC_D10
  Top 0.203: 54.27,23.84 DISPLAY.22 | IC15.66 58.12,42.06 58.72,41.46 58.72,38.44 55.06,34.79 55.06,24.63 54.27,23.84 | 54.27,23.84
FMC_D11
  Top 0.203: DISPLAY.23 56.81,17.48 55.54,18.76 55.54,34.63 59.19,38.28 59.19,41.62 58.62,42.19 IC15.67
FMC_D12
  Top 0.203: IC15.68 59.12,42.33 59.67,41.77 59.67,38.12 57.29,35.74 57.29,21.71 DISPLAY.24
FMC_D13
  Top 0.203: DISPLAY.25 59.35,17.48 58.08,18.76 58.08,24.47 57.76,24.79 57.76,35.58 60.3,38.12 61.57,38.12 63.48,40.03 63.48,43.52 64.43,44.47 64.43,47.01 64.19,47.25 IC15.77
FMC_D14
  Top 0.203: IC15.78 64.33,47.75 64.91,47.17 64.91,44.31 63.95,43.36 63.95,39.87 61.73,37.65 60.46,37.65 58.24,35.42 58.24,24.95 59.35,23.84 DISPLAY.26
FMC_D15
  Top 0.203: DISPLAY.27 61.89,17.48 60.62,18.76 60.62,23.2 58.72,25.1 58.72,35.27 60.62,37.17 61.89,37.17 64.43,39.71 64.43,43.2 65.38,44.16 65.38,47.33 64.47,48.25 IC15.79
FMC_NE1  (via drill 0.3)
  Top 0.203: v57.6,44.63 56.65,44.63 54.91,46.38 54.91,61.3 54.11,62.09 54.11,63.05 54.12,63.05 IC15.123 | DISPLAY.28 61.89,22.41 61.26,23.04 v61.26,23.52
  Bottom 0.203: v57.6,44.63 58.24,45.27 58.56,45.27 59.03,44.79 59.03,44.16 58.72,43.84 58.72,25.1 60.3,23.52 v61.26,23.52
FMC_NOE  (via drill 0.3)
  Top 0.203: IC15.118 56.62,61.9 55.86,61.14 55.86,47.33 56.17,47.01 56.17,46.06 56.97,45.27 57.92,45.27 58.4,44.79 v58.4,44.63 | v44.11,18.44 DISPLAY.13
  Bottom 0.203: v44.11,18.44 46.02,18.44 54.59,27.01 54.59,37.33 55.86,38.6 55.86,42.09 v58.4,44.63
FMC_NWE  (via drill 0.3)
  Top 0.203: DISPLAY.14 44.11,21.61 v45.06,21.61 | v55.54,46.54 55.38,46.7 55.38,61.3 56.12,62.03 IC15.119
  Bottom 0.203: v55.54,46.54 55.22,46.22 52.21,43.2 52.21,27.8 46.02,21.61 v45.06,21.61
FT_3V3  (via drill 0.3)
  Top 0.203: IC14.20 41.38,108.63 C37.1 40.52,108.5 v40.3,108.29 | IC14.31 41.75,103.14 C36.1 41.04,103.84 v40.3,103.84 | IC14.42 49.3,99.39 C38.1 50.56,98.13 51.89,98.13 54.75,100.99 v55.86,100.99 | v55.86,106.7 C39.1 55.37,106.13 IC14.56 53.54,106.13 53.32,105.91 53.32,103.37 53.55,103.14 IC14.50 | RN3.7 RN3.8 40.3,109.77 v40.3,108.29 | IC13.8 57.66,122.26 C29.1 v58.72,122.26 | R24.2 42.2,113.9 v42.2,114.96 | L14.1 53.32,115.65 53.32,116.86 | v53.95,116.86 53.32,116.86 | Q6.4 Q6.1 52.06,116.86 53.32,116.86 | IC12.2 43.33,119.4 44.64,119.4 C28.1 45.16,119.09 v45.7,119.09 45.7,119.64 46.17,120.12 | L15.1 42.2,115.86 v42.2,114.96 | 46.17,120.12 46.17,121.24 | 46.17,120.12 RN2.8 | 46.17,121.24 RN2.6 | 46.17,121.24 46.17,121.62 46.41,121.87 RN2.5 | v40.3,108.29 39.66,108.92 39.66,113.05 41.57,114.96 v42.2,114.96
  Bottom 0.203: v40.3,108.29 40.94,107.66 40.94,104.48 v40.3,103.84 | v58.72,122.26 58.08,121.62 52.37,121.62 49.83,119.09 v45.7,119.09 42.2,115.59 v42.2,114.96 52.05,114.96 v53.95,116.86 57.13,113.69 57.13,111.78 55.86,110.51 v55.86,106.7 v55.86,100.99
GND  (via drill 0.3)
  Top 0.203: IC25.41 35.42,28.32 34.74,27.65 | 34.74,27.65 34.74,26.69 34.16,26.11 C77.2 35.06,25.16 | 36.92,36.22 IC25.17 | 36.92,36.22 36.92,34.74 IC25.TH | 37.92,36.38 37.76,36.22 36.92,36.22 | IC25.21 34.92,39.37 34.27,40.03 30.77,40.03 26.01,44.79 24.89,44.79 R50.1 | IC29.21 71.39,24.17 72.05,23.52 78.08,23.52 81.41,20.19 R56.1 | 69.39,27.65 69.39,29.12 IC29.TH | 69.39,27.65 IC29.17 | 68.39,27.48 68.56,27.65 69.39,27.65 | IC29.41 70.89,35.54 71.41,36.06 71.41,37.7 C86.2 71.15,38.81 | IC15.107 64.53,62.25 C44.2 64.96,62.25 65.91,62.25 | 65.91,62.25 C48.2 | 65.91,62.25 66.02,62.15 v66.02,61.14 | IC15.94 65,55.75 C49.2 65.8,54.95 v66.65,54.95 | IC15.83 64.16,50.25 C50.2 64.85,49.71 v65.7,49.71 | IC15.61 55.62,40.95 C53.2 54.59,39.92 v54.59,39.08 | IC15.51 50.62,40.56 C52.2 49.67,39.61 v49.67,38.76 | IC15.38 44.12,42.47 C51.2 | C51.2 43.16,41.51 | C55.2 38.29,47.17 | C55.2 38.5,47.17 39.61,47.17 C54.2 40.62,47.75 IC15.31 | C55.2 38.34,47.07 v37.44,47.97 38.34,48.86 C41.2 | v39.03,56.22 39.88,56.22 C56.2 40.85,55.25 IC15.16 | IC15.138 46.62,65.68 C46.2 46.17,66.48 v46.17,67.33 | IC15.130 50.62,66.64 C47.2 50.94,66.96 v50.94,67.65 | IC15.120 55.62,65.76 C42.2 | C42.2 56.33,66.48 | Q7.2 36.53,52.09 v35.7,52.09 | E20.GND v44.11,37.17 | IC2.8 96.5,106.05 C4.2 | C4.2 | C4.2 v96.5,104.8 | IC3.1 101.87,108.31 102.21,107.97 102.21,106.38 | 102.21,106.38 102.21,105.22 C3.2 C8.2 C7.2 100.62,103.42 | IC3.4 101.24,106.38 102.21,106.38 | 100.62,103.42 100.73,103.53 | IC6.2 94.38,100.03 C6.2 95.23,97.91 C15.2 95.23,97.81 v95.23,96.86 | IC21.21 34.61,92.71 33.95,93.37 29.5,93.37 26.96,95.91 25.06,95.91 24.74,96.22 R44.1
  Top 0.203: IC21.17 36.61,88.92 | 36.61,88.92 36.61,88.09 IC21.TH | 37.61,89.09 37.44,88.92 36.61,88.92 | IC21.41 35.11,81.5 34.74,81.14 34.74,79.66 | 34.74,79.66 C68.2 33.95,79.3 v33.95,80.03 | C66.2 35.06,79.66 34.74,79.66 | IC33.21 28.25,111.92 27.6,112.58 23.95,112.58 23.16,113.37 23.16,114.64 21.25,116.55 20.13,116.55 R62.1 18.37,118.26 | 45.22,113.69 46.3,112.6 IC14.13 46.3,111.49 46.65,111.15 46.97,111.15 47.3,111.48 IC14.11 IC14.10 | 45.22,113.69 C32.2 45.3,113.55 IC14.15 45.3,112.73 | 45.22,113.69 45.22,114.38 C34.2 45.22,115.01 v45.22,115.91 | IC14.51 55.55,103.64 C39.2 56.28,103.53 v57.13,103.53 57.13,102.79 C30.2 | IC13.5 57.66,118.45 C29.2 v58.72,118.45 | 41.92,106.13 IC14.25 | C37.2 41.92,106.13 | 41.25,105.47 C36.2 | 41.92,106.13 41.25,105.47 | 41.25,105.47 40.65,106.07 v40.3,106.07 40.62,106.07 41.25,106.7 | IC14.35 45.8,100.04 C31.2 44.11,99.82 v44.11,100.03 | RN3.5 40.62,111.84 v40.62,112.42 | USB1.5 33,118.78 v33,117.5 | IC14.47 51.8,99.58 C38.2 51.79,99.56 v52.37,99.56 | IC14.5 50.3,110.83 50.78,110.35 51.73,110.35 52.3,110.93 IC14.1 52.3,113.41 R26.1 53.22,113.05 v53.95,113.05 | C33.2 53.95,112.2 v53.95,113.05 | C35.2 53.95,114.22 v53.95,113.05 | IC17.21 72.98,75.29 73.64,74.64 78.4,74.64 79.99,76.22 82.36,76.22 R38.1 | IC17.41 72.48,86.66 73.32,87.49 73.32,88.82 C59.2 73,89.98 v73,90.19 73,89.98 C57.2 | IC17.17 70.98,80.55 IC17.TH | IC17.TH 69.98,79.55 | R36.1 76.44,72.04 v76.5,72.09 | R35.1 C63.2 R34.1 67.13,71.56 v67.13,70.83 | v33.95,114.64 33.89,114.7 R59.1 C99.2 R60.1 | IC33.41 28.75,100.71 28.23,100.19 28.23,98.71 C95.2 27.92,98.19 v27.92,97.34 28.97,97.34 C93.2
  Top 0.203: E22.GND v40.46,99.08 E23.GND | E19.GND v39.98,77.17 | 30.25,106.82 IC33.17 | IC33.TH 30.25,106.82 | 30.25,106.82 31.25,107.82 | E8.GND v73.32,55.9 E7.GND | E21.GND 68.24,40.66 v68.88,40.03 | E14.GND v69.19,43.52 | v12.36,71.78 E3.GND | v12.36,66.7 E1.GND | v21.89,61.94 E18.GND | C17.2 v26.01,54.95 | C90.2 59.98,28.28 v59.35,28.28 | R53.1 C90.2 | C90.2 R54.1 | R55.1 v59.35,34.63 | 71.15,38.81 71.1,38.86 v71.1,39.08 | C84.2 71.05,38.81 71.15,38.81 | C87.2 66.28,36.06 v65.38,36.06 | C72.2 R41.1 R42.1 v36.17,96.86 | R48.1 C81.2 R47.1 40.09,43.2 v40.94,43.2 | 24.69,115.28 R61.1 24.37,114.96 v23.79,114.96 | E4.GND v69.83,106.7 | v84.11,99.72 83.8,99.72 82.84,98.77 C16.2 82.69,98.61 81.89,99.4 IC7.3 | E15.GND 48.71,94.16 v48.08,93.53 | 62.68,40.61 C40.2 62.21,40.45 v62.21,39.71 | v33.31,98.77 C96.2 | v33.31,98.77 | R43.1 31.35,95.91 v30.46,95.91 | 35.06,25.16 C75.2 | 35.06,25.16 v35.06,25.1 35.06,25.16 | 34.74,27.65 | v40.3,24.15 41.2,24.15 C22.2 41.36,21.45 DISPLAY.12 | C85.2 84.41,20.19 | R49.1 31.94,43.2 v31.09,43.2 | v88.88,42.25 M4.7 | IC17.TH | IC17.TH v72.37,80.67 | C60.2 68.03,87.34 v68.88,87.34 | E9.GND v61.73,79.4 | R37.1 v35.54,76.54 | E16.GND v72.37,64.47 | M2.7 14.58,77.49 v12.68,77.49 | M3.7 v12.52,29.55 | M3.7 | E13.GND v48.87,30.82 | v49.19,116.86 50.13,116.86 Q6.2 | IC12.1 41.19,119.5 C27.2 39.4,119.24 39.66,119.29 v39.66,118.45 | C28.2 44.64,121.31 v43.79,121.31 | E11.GND v23.79,12.72 | IC33.TH | E2.GND v78.08,103.53 | ENC2.3 6.8,81.62 5.22,83.21 5.22,83.68 v4.42,84.48 | ENC1.3 v101.9,86.38 | v56.17,67.49 56.17,66.44 C42.2 | C25.2 C26.2 | C25.2 | C25.2 52.1,72.09 v53,72.09 53,73.1 C23.2 54.25,74.35 IC11.18 54.25,76.22 | USB.MNT2 59.37,114.62 v59.35,114.64
  Top 0.203: USB.MNT1 74.57,114.62 v74.59,114.64 | USB.4 v63.48,111.62 | Q3.2 | v87.29,106.38 C5.2 | C5.2 | C2.2 | C2.2 v87.29,102.73 | v100.78,102.73 100.78,103.27 100.62,103.42 | MSL.P$1 4.37,38.49 v3.79,39.08 | E5.GND v99.04,44.16 99.35,44.16 99.72,43.79 MSR.P$1 | 54.25,76.22 IC11.1 | IC11.11 54.22,76.25 54.25,76.22 | C24.2 v48.55,71.14 | v36.65,59.55 37.39,59.55 C45.2 | v61.57,39.08 60.72,39.08 C43.2 | v65.54,20.02 64.43,20.02 DISPLAY.30 | v42.84,42.57 42.84,42.03 C51.2 | E17.GND 63.8,74.95 63.48,74.64 v63.48,74 | E12.GND v58.4,74 | E12.GND | ENC4.3 98.4,29.23 99.67,29.23 v99.67,29.87 | E6.GND v8.23,44.16 | v9.03,27.8 9.03,28.76 8.87,28.91 ENC3.3 | v58.72,118.45 | v83.64,108.29 83.64,107.81 84.11,107.34 C1.2 84.42,107.54 IC1.1 IC1.2 | R12.1 v89.35,102.58 | IR2.P$3 98.64,97.83 C19.2 98.72,97.71 v98.72,96.86 | LED1.C v105.07,13.36 | v100.31,16.85 102.71,16.85 PWR.1 | RESET.2 3.29,16.85 v5.69,16.85 | E10.GND 56.49,79.4 v56.17,79.72 | C78.2 42.2,30.13 v42.2,30.82
  Top 0.305: M5.5 v6.65,105.43 | IC8.2 74.59,107.02 75.22,106.38 75.22,105.33 R18.1 73.74,105.11 v73.32,105.11 73.32,105.38 C18.2
  Top 0.406: C17.2 26.86,53.89 27.92,54.95 IC9.4 | IC10.2 81.89,59.71 81.26,59.08 79.04,59.08 R22.2 78.72,59.08 v79.67,60.03 | C69.2 v39.66,80.03 | M1.7 v93.32,92.1 | Q4.2 71.73,48.06 R21.1 v72.69,47.97 | C21.2 v19.03,12.09 | NRF24.1 20.14,9.71 20.14,12.09 | Q3.2 v13.63,96.54 | SD.COM2 88.64,72.41 v90.15,72.41 | v107.93,74.64 109.52,74.64 SD.COM4 | SD.COM1 88.66,46.7 v90.15,46.7 | SD.COM3 109.52,46.7 v107.93,46.7 | IC21.TH
  Top 0.61: SD.6 87.38,55.04 88.24,55.9 88.24,61.94 87.64,62.54 SD.3 84.82,62.54 84.64,62.36 | 84.64,62.36 C20.2 | v84.43,63.2 84.43,62.57 84.64,62.36 | v49.67,87.34 49.67,88.77 EXT.9
  Bottom 0.203: v101.9,36.53 101.9,35.9 100.9,34.9 M4B.5 | v101.9,86.38 101.9,85.43 101.21,84.75 M1B.5 | M2B.5 4.47,84.53 v4.42,84.48 | M3B.5 4.47,36.9 v4.42,36.85
  other vias: 36.17,33.99 19.66,44.79 70.14,29.87 35.86,87.34 87.45,77.17 29.51,106.07 30.93,69.24 31.73,69.24 30.14,69.24 19.98,95.91 13.79,118.77 86.97,20.66 19.66,45.58 18.87,45.58 18.87,44.79 86.97,19.71 86.18,19.71 86.18,20.66 88.24,77.17 87.45,76.22 88.24,76.22 12.99,118.77 12.99,117.81 13.79,117.81 19.98,96.86 19.19,95.91 19.19,96.86 13.31,57.17 13.31,56.22 14.27,56.22 14.27,57.17 67.92,95.59 53.95,95.91 56.65,94.48 56.65,95.27 67.61,102.58 67.61,101.78 67.29,96.54 68.56,96.54 68.56,94.64 67.29,94.64 65.07,93.37 61.57,96.22 35.86,88.92 34.27,88.92 34.27,87.34 73.96,80.67 73.96,79.08 72.37,79.08 72.05,29.87 72.05,27.96 70.14,27.96 36.17,35.9 34.27,35.9 34.27,33.99 29.51,107.97 27.6,107.97 27.92,106.07
  pour Top (isolate 0.254, rank 6, no thermals): 53.32,99.08 54.27,100.03 57.45,100.03 58.72,101.31 59.67,101.31 62.52,104.16 71.41,104.16 72.69,102.89 72.69,93.37 71.41,92.1 69.83,92.1 68.56,90.83 57.76,90.83 55.86,92.73 54.59,92.73 53.32,94
  pour Top (no thermals): 29.82,70.83 29.82,68.28 30.14,67.97 31.73,67.97 32.05,68.28 32.05,70.83
  pour Top (no thermals): 18.71,46.06 18.39,45.74 18.39,44.79 18.71,44.47 25.06,44.47 25.06,46.06
  pour Top (no thermals): 87.29,19.39 87.61,19.71 87.61,20.66 87.29,20.98 80.94,20.98 80.94,19.39
  pour Top (no thermals): 88.56,75.91 88.88,76.22 88.88,77.17 88.56,77.49 82.21,77.49 82.21,75.91
  pour Top (no thermals): 12.68,119.09 12.36,118.77 12.36,117.81 12.68,117.5 19.03,117.5 19.03,119.09
  pour Top (no thermals): 19.03,97.18 18.71,96.86 18.71,95.91 19.03,95.59 25.38,95.59 25.38,97.18
  pour Top (no thermals): 1.56,56.86 5.06,56.86 6.33,58.12 13.63,58.12 14.58,57.17 14.58,56.22 14.27,55.9 11.41,53.05 1.25,53.05 1.25,56.86
IMU_CS  (via drill 0.3)
  Top 0.203: IC15.126 52.62,63.59 v52.84,63.36 | v56.02,69.56 56.93,70.47 E12.3
  Bottom 0.203: v52.84,63.36 52.84,64.63 55.06,66.86 55.06,68.6 v56.02,69.56
IR_ADC
  Top 0.203: IC7.5 82.89,100.38 86.31,100.38 90.47,96.22 95.55,96.22 96.92,97.6 C19.1 R19.2
IR_LED  (via drill 0.3)
  Top 0.203: Q3.1 v13.63,94.64 | v18.08,76.22 18.08,75.59 28.23,65.43 v33.95,65.43 | IC15.137 47.12,67.19 46.33,67.97 44.11,67.97 39.66,63.52 39.35,63.52 38.71,62.89 36.49,62.89 35.86,62.25 v33.95,62.25
  Bottom 0.203: v13.63,94.64 17.12,91.14 17.12,77.17 v18.08,76.22 | v33.95,62.25 v33.95,65.43
IVCC-ADC
  Top 0.203: C2.1 R6.2 82.89,104.16 IC7.6
JTCK  (via drill 0.3)
  Top 0.203: E15.4 50.58,92.93 51.41,92.1 v52.37,92.1 | IC15.109 61.12,64.16 v61.73,64.16 | v59.03,79.87 59.03,79.48 E10.7
  Bottom 0.203: v61.73,64.16 63.48,64.16 64.59,65.27 64.59,70.35 63.48,71.46 63.48,72.57 59.98,76.06 | 59.19,79.87 59.19,81.46 52.37,88.29 v52.37,92.1 | 59.19,79.87 v59.03,79.87 | 59.98,76.06 | 59.98,76.06 59.19,76.86 59.19,79.87
JTCK1  (via drill 0.3)
  Top 0.203: 44.8,111.78 44.8,111.09 50.14,105.75 v50.14,101.78 | 44.8,111.78 IC14.16 | RN3.4 41.46,111.78 44.8,111.78 | v51.09,96.86 51.09,96.54 50.58,96.03 E15.3
  Bottom 0.203: v50.14,101.78 50.14,100.99 51.09,100.03 v51.09,96.86
JTD-A2M1  (via drill 0.3)
  Top 0.203: RN3.2 41.98,110.58 42.42,110.13 IC14.17 44.8,110.13 49.35,105.59 v49.35,102.58 | v49.83,96.86 49.83,96.54 49.78,96.5 E15.7
  Bottom 0.203: v49.83,96.86 49.83,99.08 48.71,100.19 48.71,102.1 49.19,102.58 v49.35,102.58
JTD-E2A1  (via drill 0.3)
  Top 0.203: IC14.18 44.35,109.63 48.71,105.27 48.71,102.42 v49.35,101.78 | v50.46,97.5 50.46,96.54 50.18,96.27 E15.5
  Bottom 0.203: v50.46,97.5 50.46,99.72 49.35,100.83 v49.35,101.78
JTD_A2M  (via drill 0.3)
  Top 0.203: E15.8 49.78,92.46 51.41,90.83 v53,90.83 | IC15.110 60.62,63.53 v60.78,63.36
  Bottom 0.203: v60.78,63.36 60.94,63.52 63.48,63.52 65.06,65.11 65.06,70.51 63.95,71.62 63.95,72.73 59.67,77.02 59.67,81.62 53.32,87.97 53.32,90.51 v53,90.83
JTD_E2A  (via drill 0.3)
  Top 0.203: E15.6 50.18,92.69 51.41,91.46 55.22,91.46 v55.86,90.83 | E9.5 60.82,78.25 v61.26,77.81
  Bottom 0.203: v61.26,77.81 61.1,77.97 61.1,82.1 55.86,87.34 v55.86,90.83
JTD_M2E  (via drill 0.3)
  Top 0.203: E9.7 61.22,78.44 61.57,78.44 61.89,78.13 61.89,75.75 61.41,75.27 61.41,74.95 60.62,74.16 59.35,72.89 v59.19,72.89 | IC15.133 49.12,63.91 49.67,63.36 v50.46,63.36
  Bottom 0.203: v50.46,63.36 52.37,65.27 52.37,67.33 56.81,71.78 58.56,71.78 59.19,72.41 v59.19,72.89 | v59.19,72.89
JTMS  (via drill 0.3)
  Top 0.203: IC15.105 62.1,61.25 v61.57,61.78 | 60.02,78.44 E9.1 60.02,77.46 v60.46,77.02 | E15.2 50.98,93.53 51.89,93.53 v52.05,93.37
  Bottom 0.203: v52.05,93.37 53.95,91.46 53.95,87.97 60.14,81.78 60.14,77.33 v60.46,77.02 61.26,76.22 62.05,76.22 62.37,75.91 65.7,72.57 65.7,71.78 66.49,70.98 66.49,66.86 67.29,66.06 67.29,64.47 64.59,61.78 v61.57,61.78
JTMS1  (via drill 0.3)
  Top 0.203: v48.08,103.53 48.08,104.96 43.9,109.13 IC14.19 42.15,109.13 41.38,109.9 RN3.1 | v52.05,96.86 50.98,95.8 E15.1
  Bottom 0.203: v48.08,103.53 49.19,103.53 50.78,101.94 50.78,100.99 51.73,100.03 51.73,97.18 v52.05,96.86
KICK_ERR  (via drill 0.3)
  Top 0.203: v30.46,59.39 35.22,59.39 36.33,58.28 36.65,57.97 40.3,57.97 40.58,58.25 IC15.10 | v14.58,71.14 14.55,71.11 E3.7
